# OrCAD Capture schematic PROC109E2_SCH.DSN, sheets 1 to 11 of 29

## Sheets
1 01. TABLE OF CONTENTS: title: TABLE OF CONTENTS; rev: E2
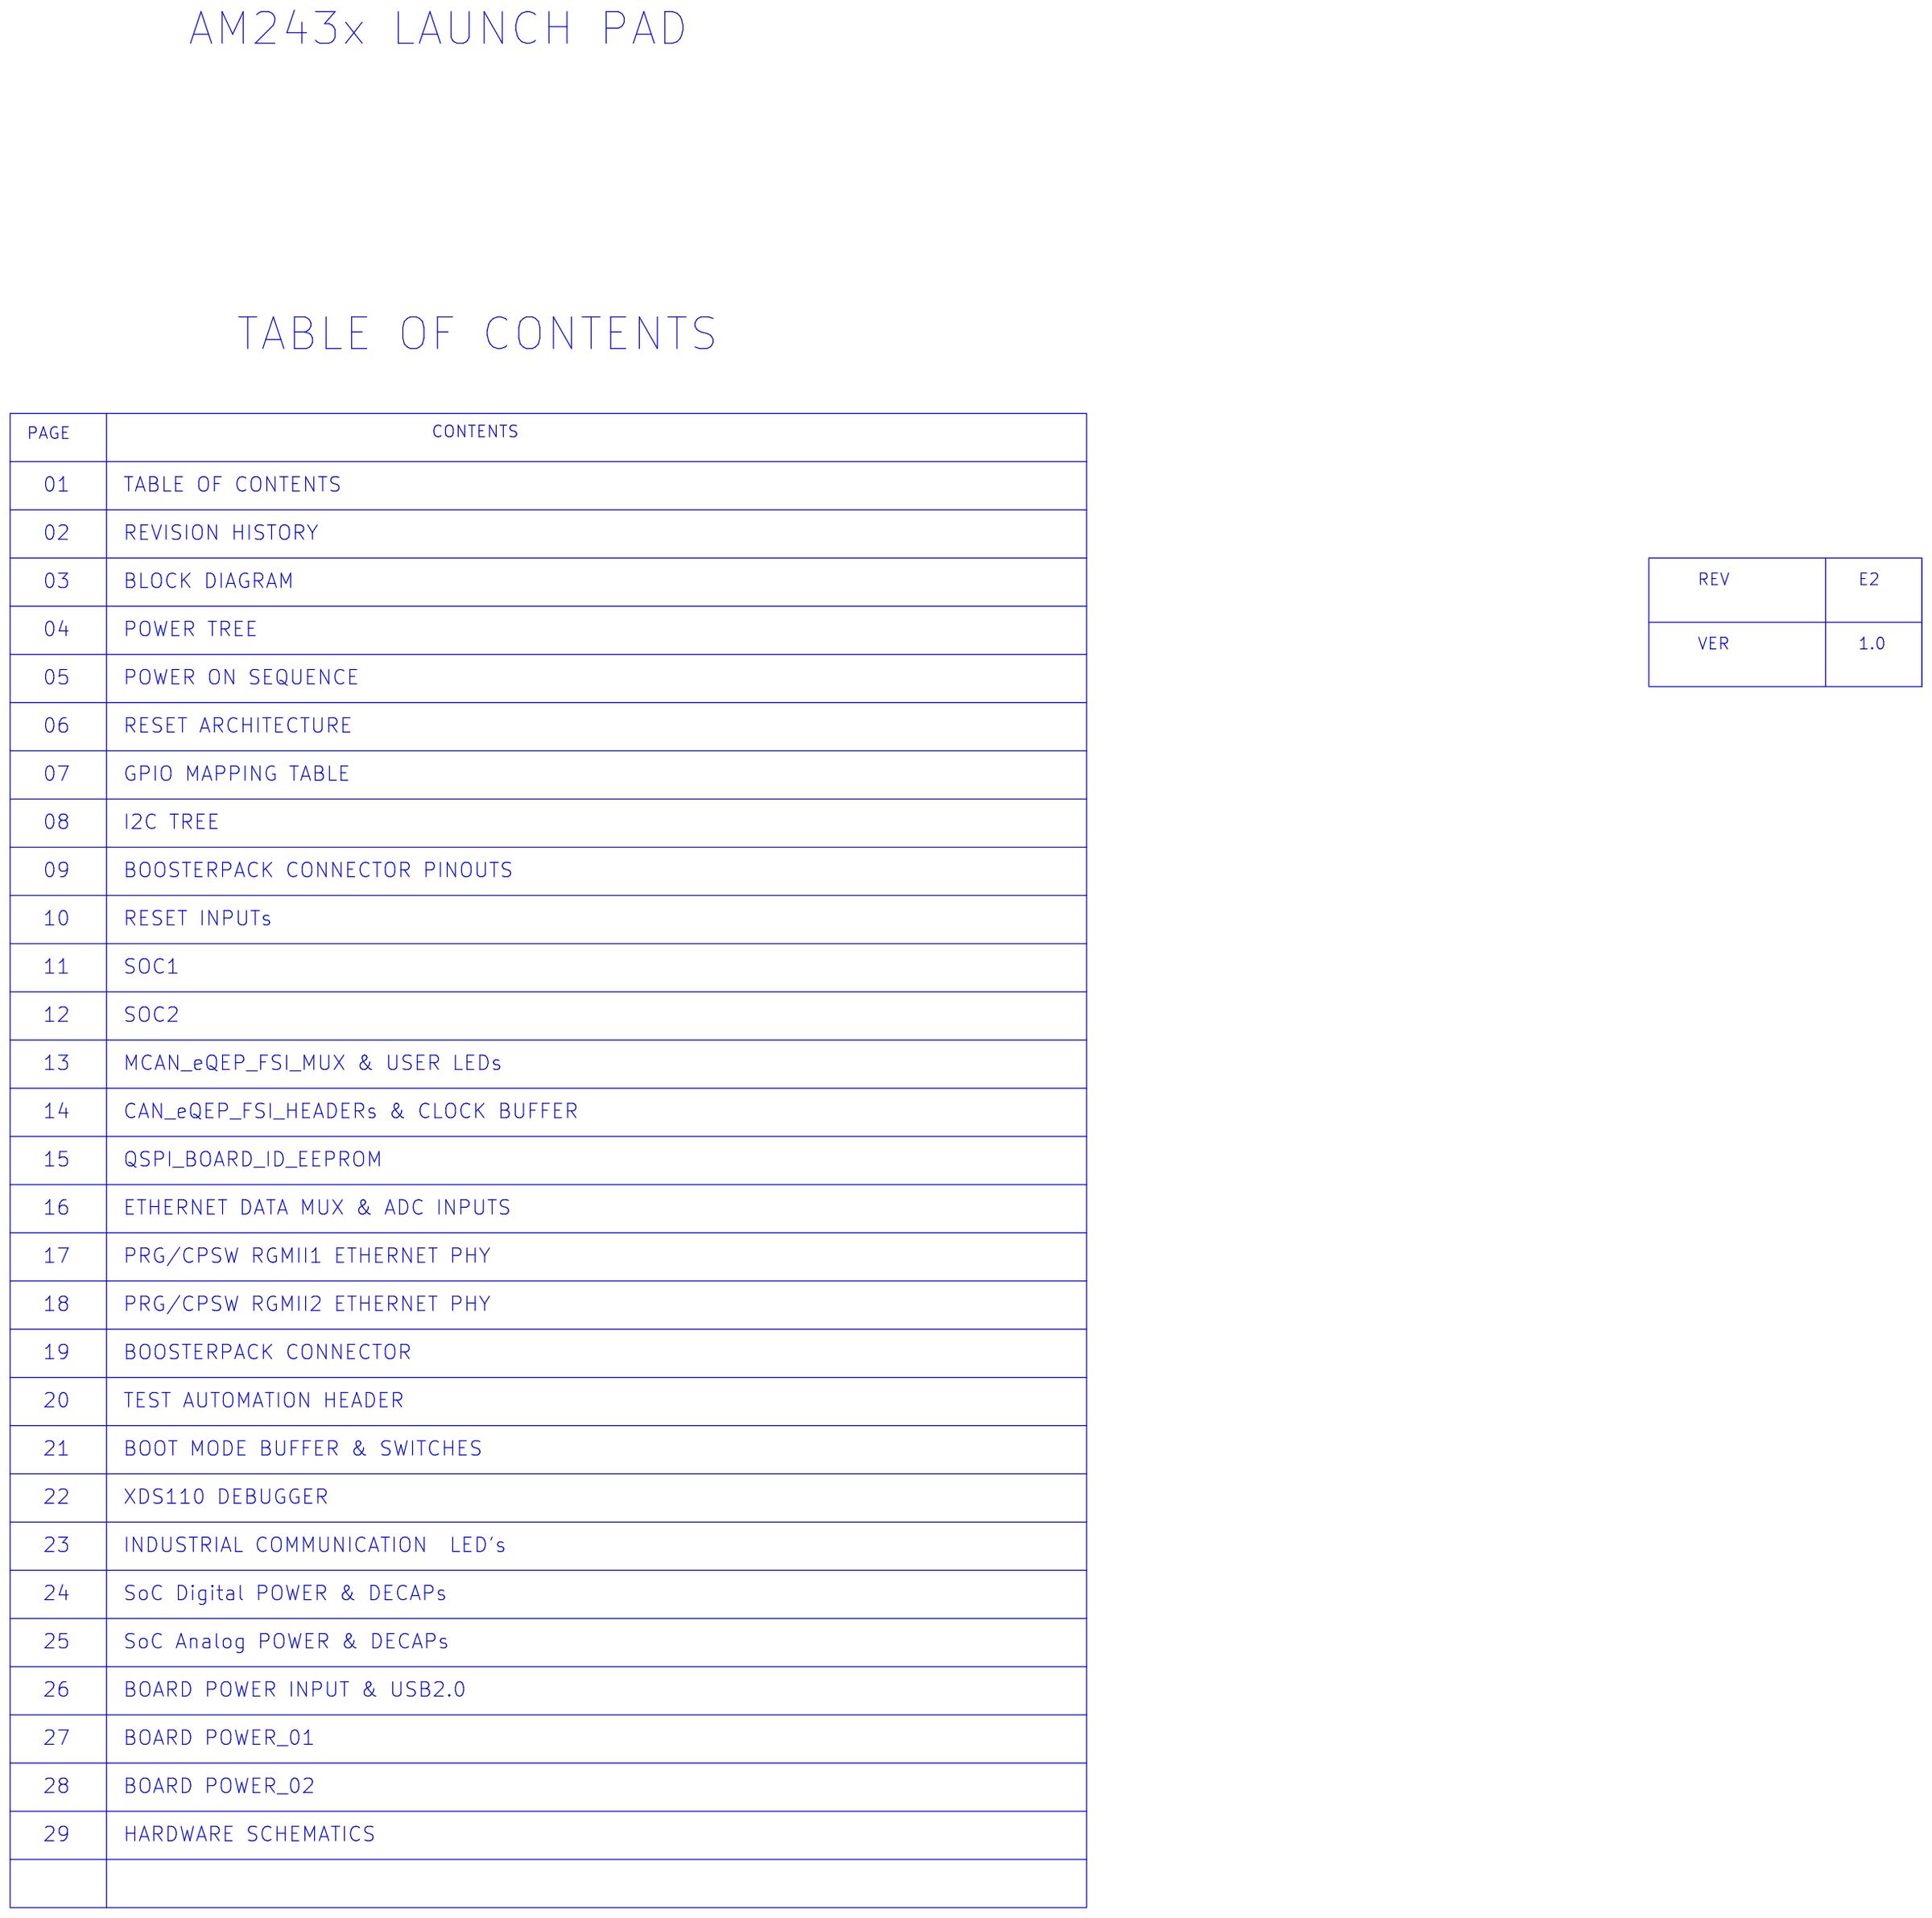
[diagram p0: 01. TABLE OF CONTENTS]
2 02. REVISION HISTORY: title: REVISION HISTORY
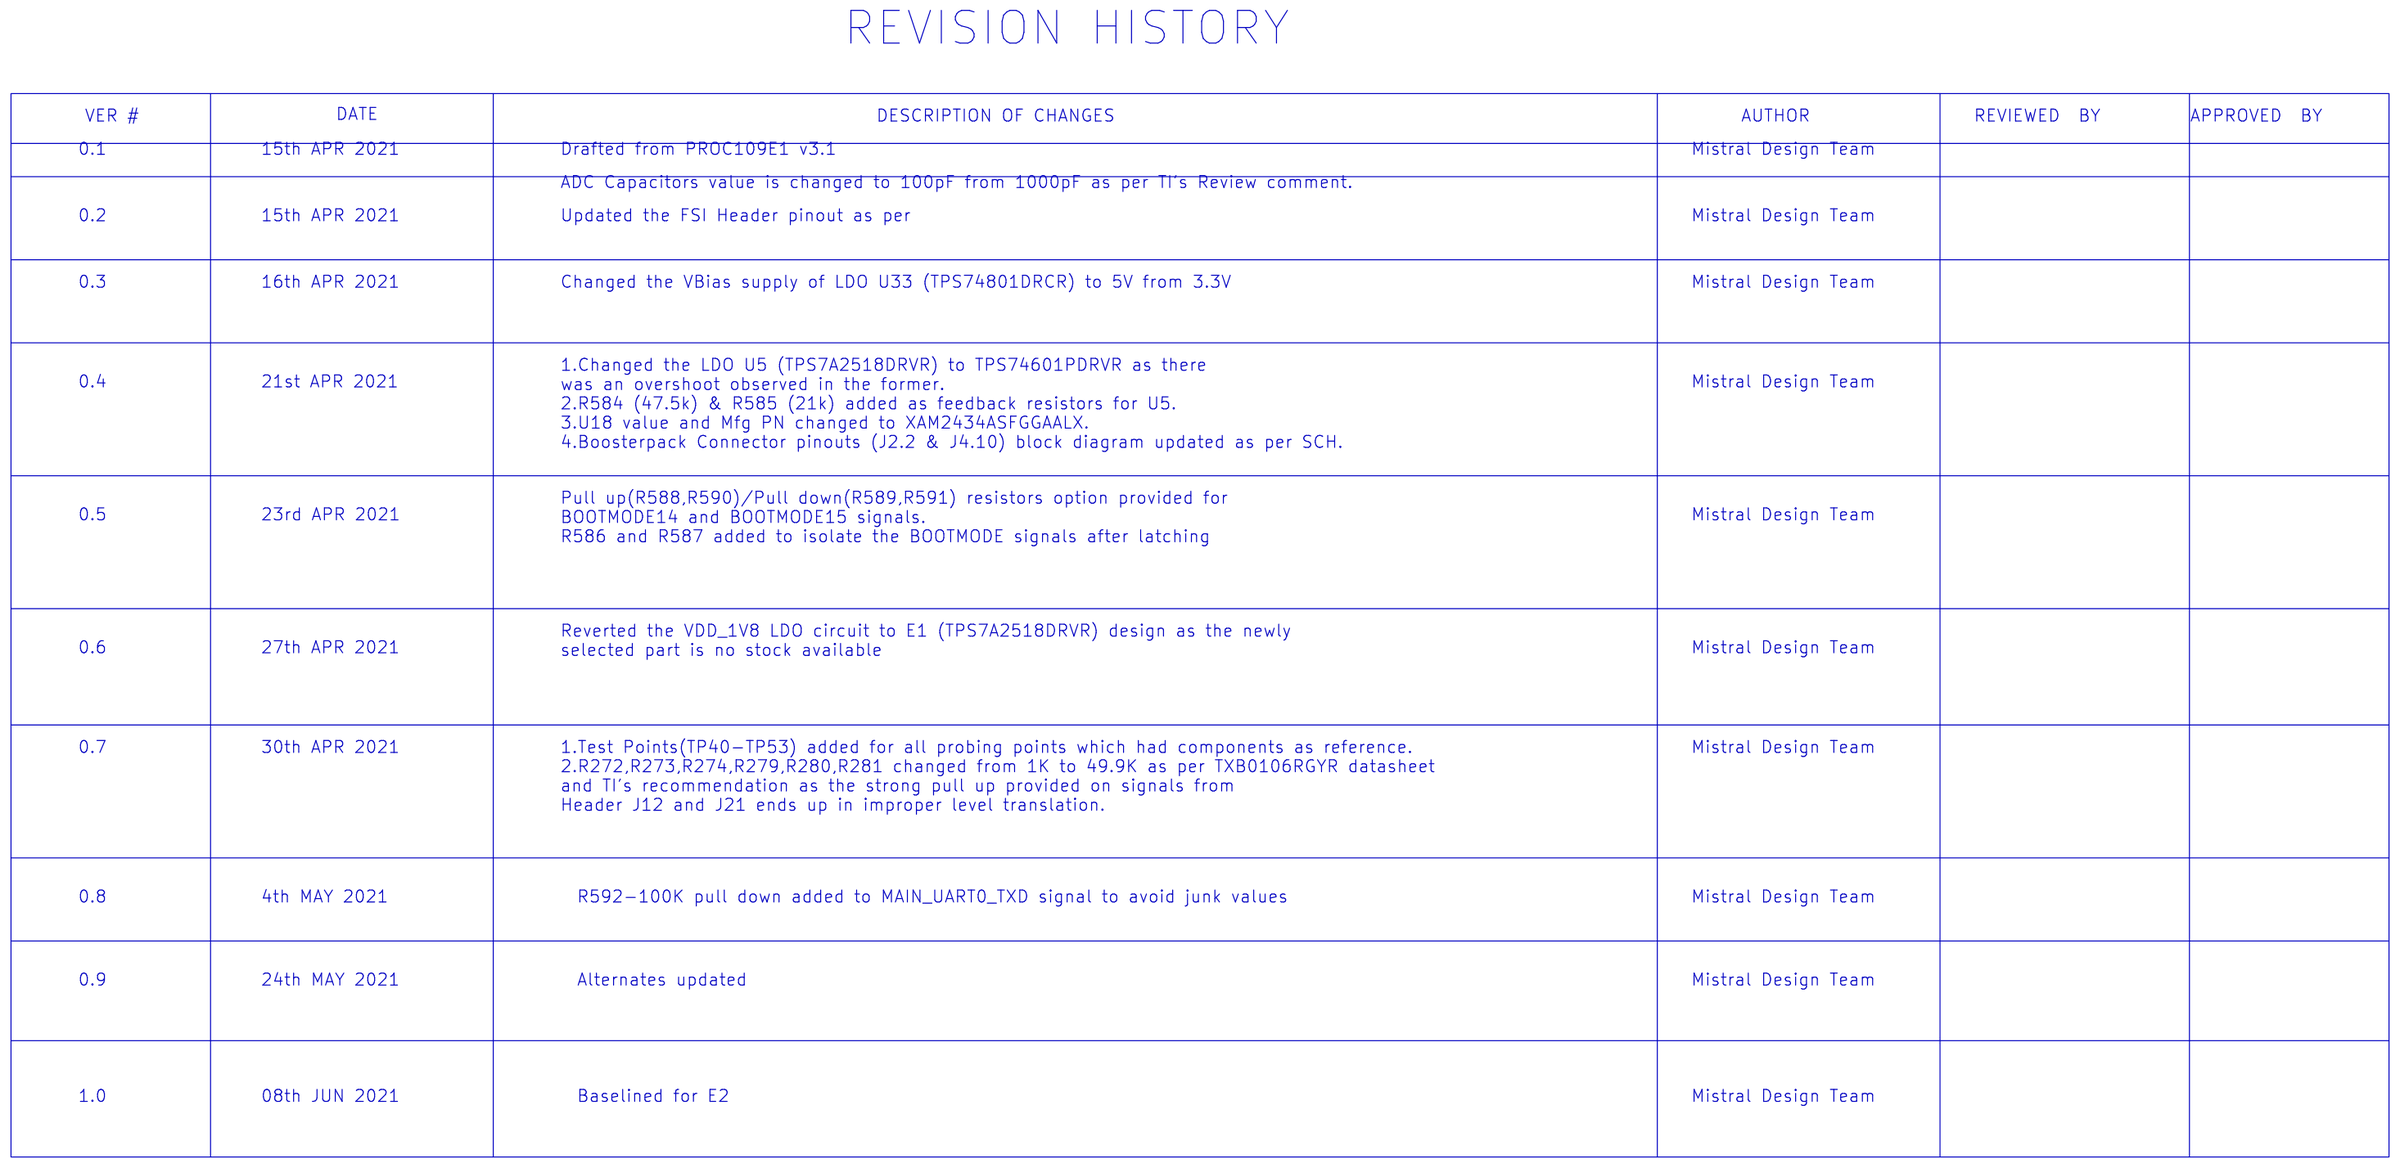
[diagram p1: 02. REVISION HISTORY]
3 03. BLOCK DIAGRAM: title: BLOCK DIAGRAM
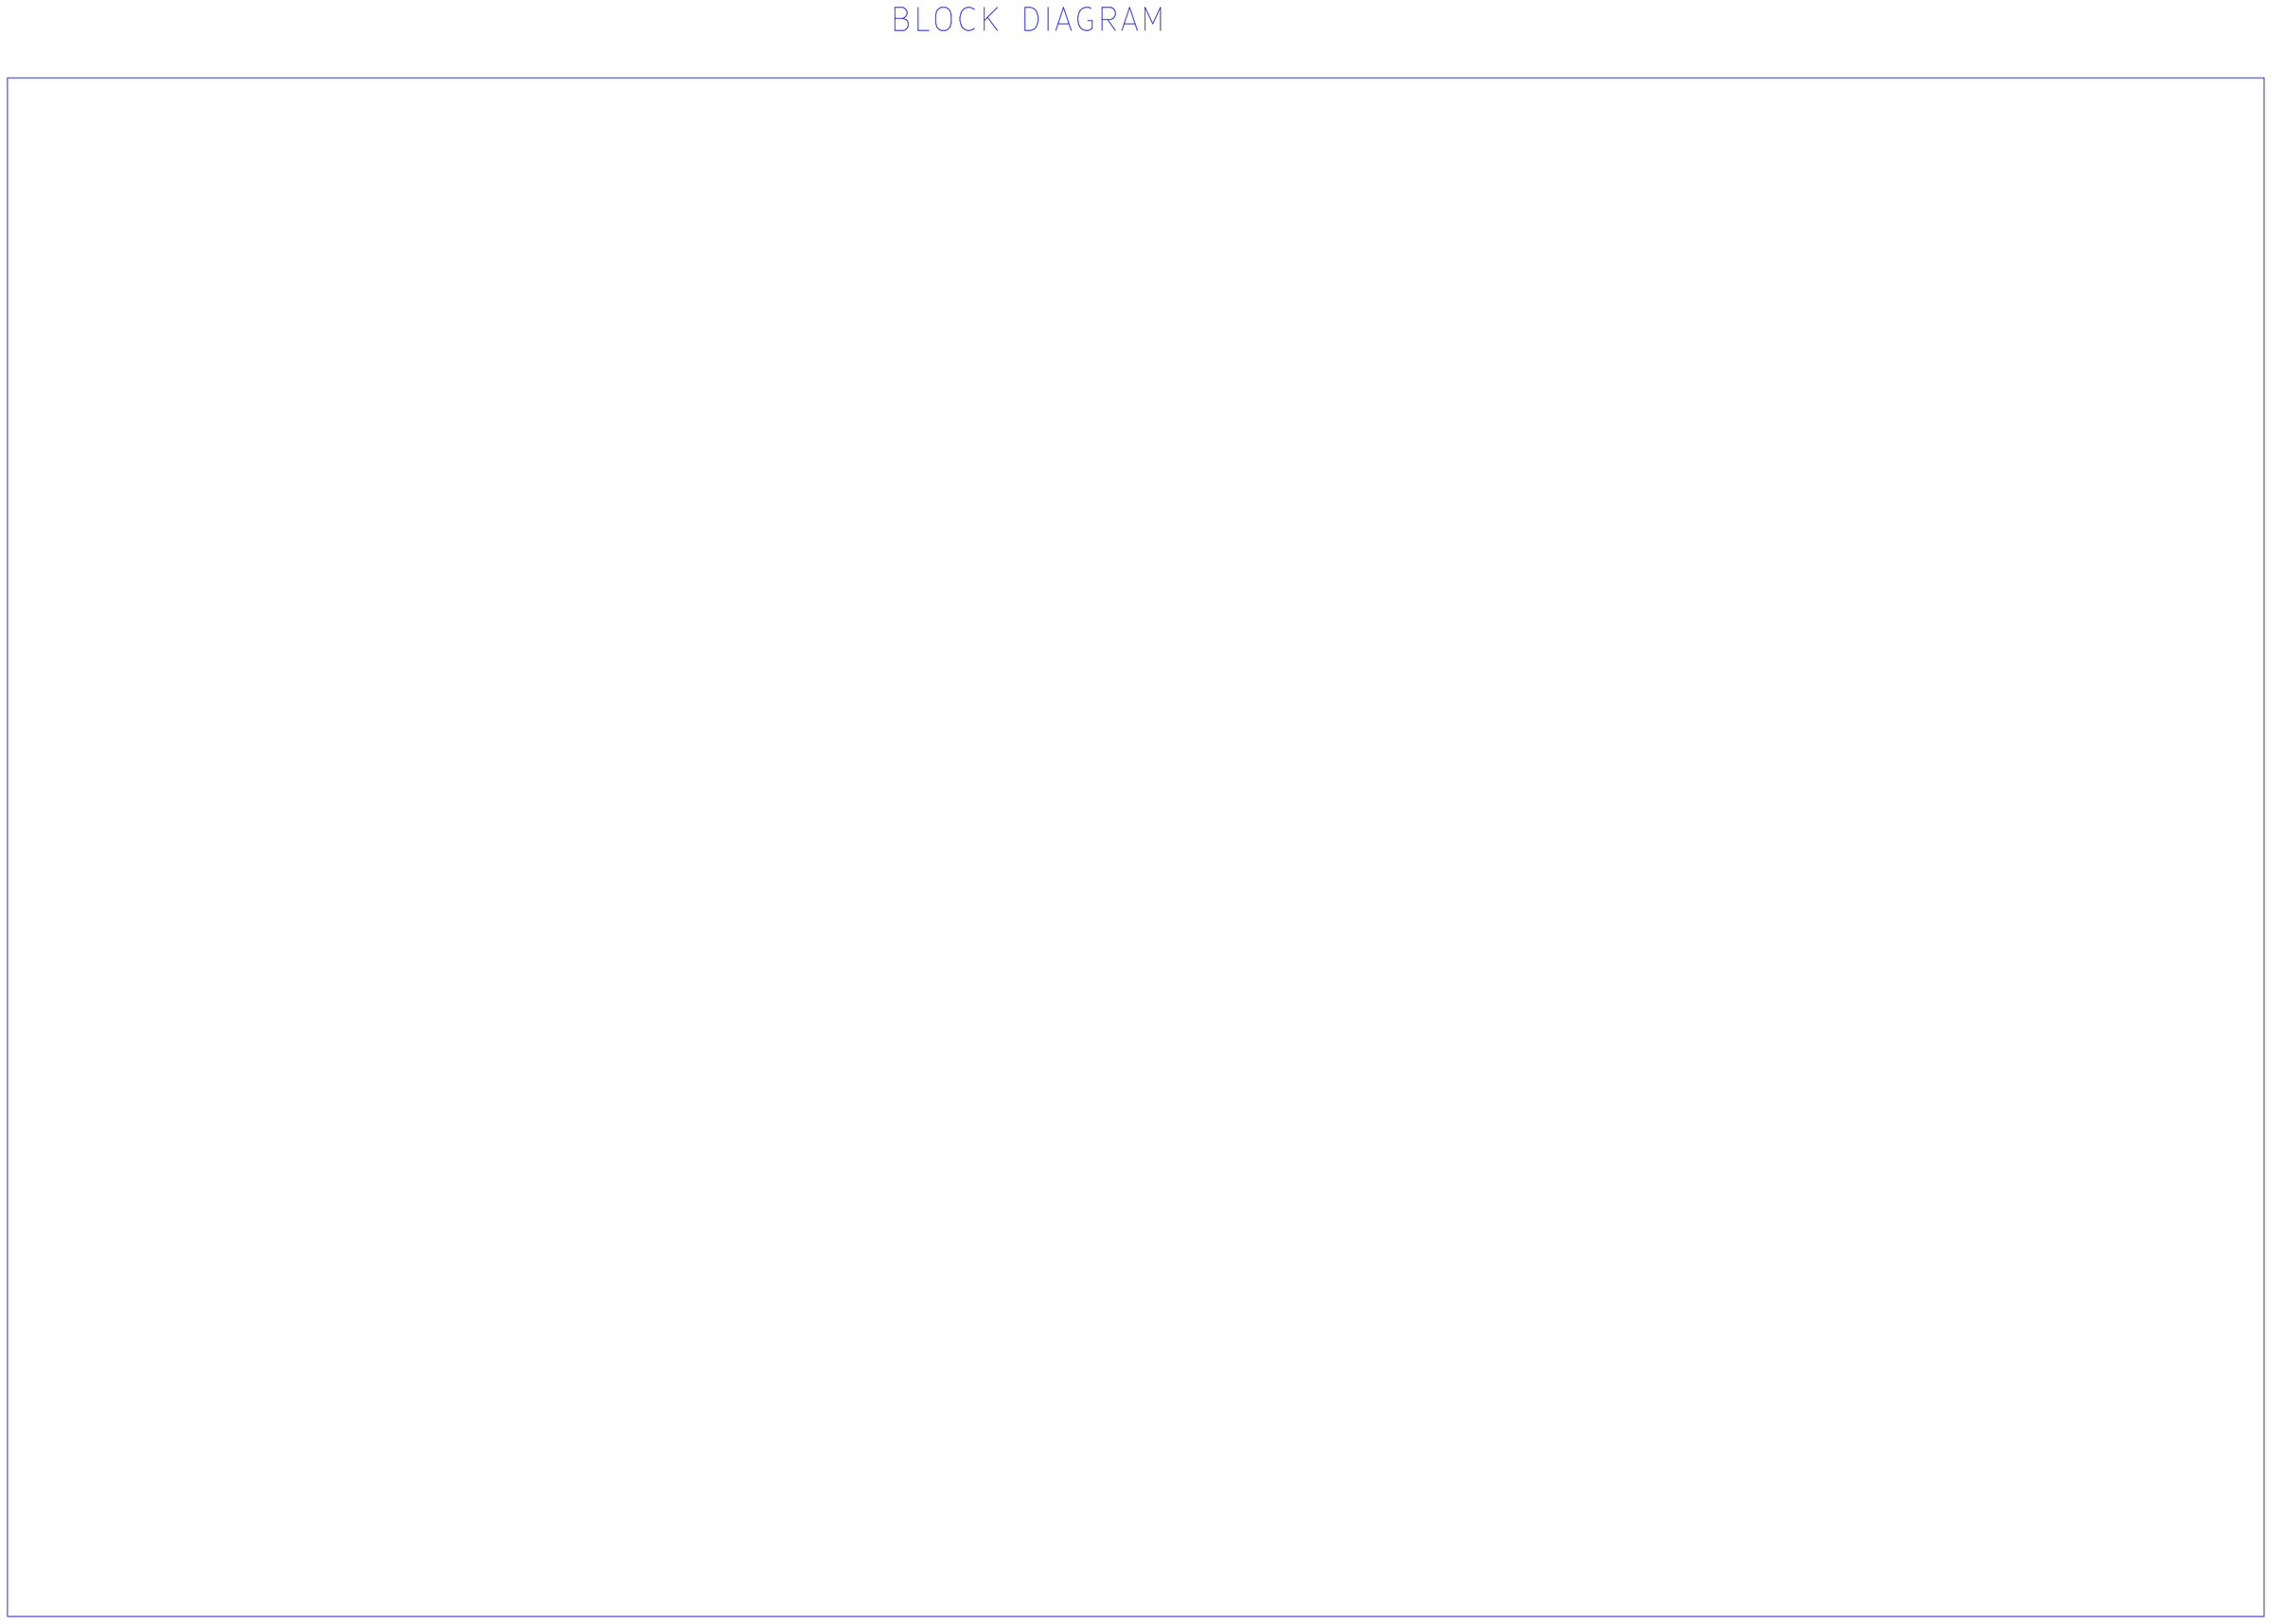
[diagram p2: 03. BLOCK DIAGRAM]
4 04. POWER TREE: title: POWER TREE
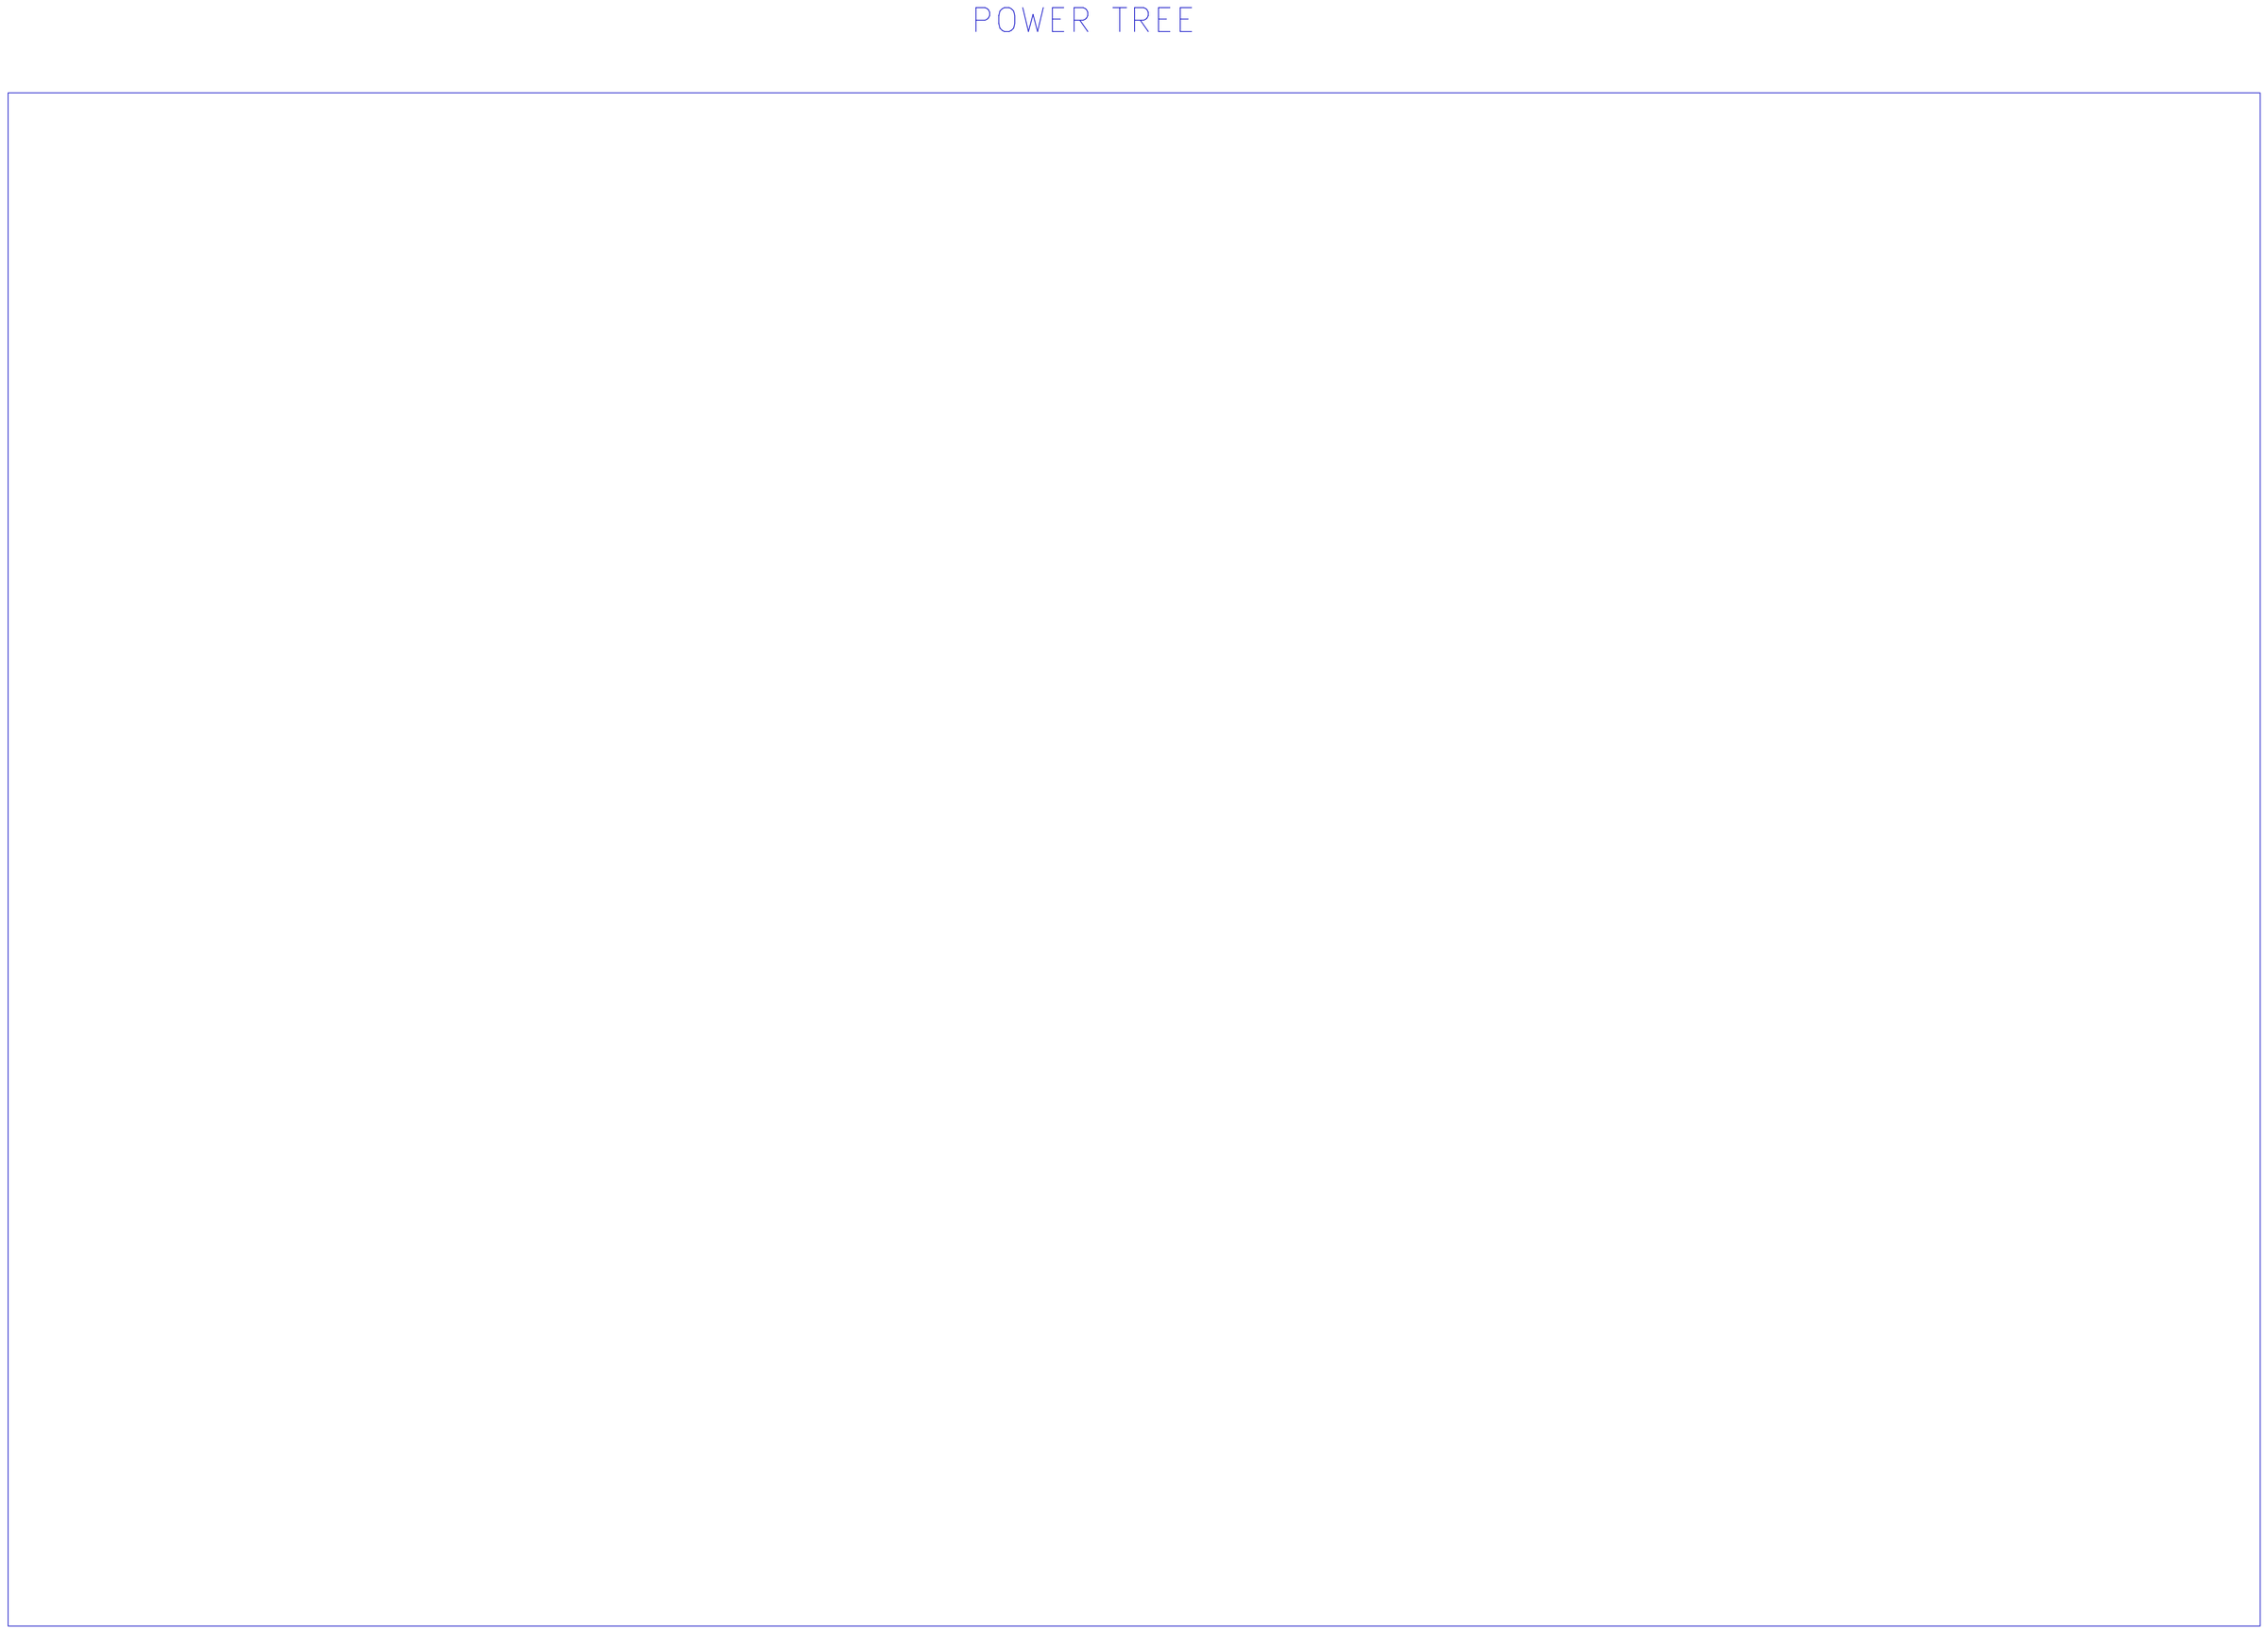
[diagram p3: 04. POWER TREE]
5 05. POWER ON SEQUENCE: title: POWER ON SEQUENCE
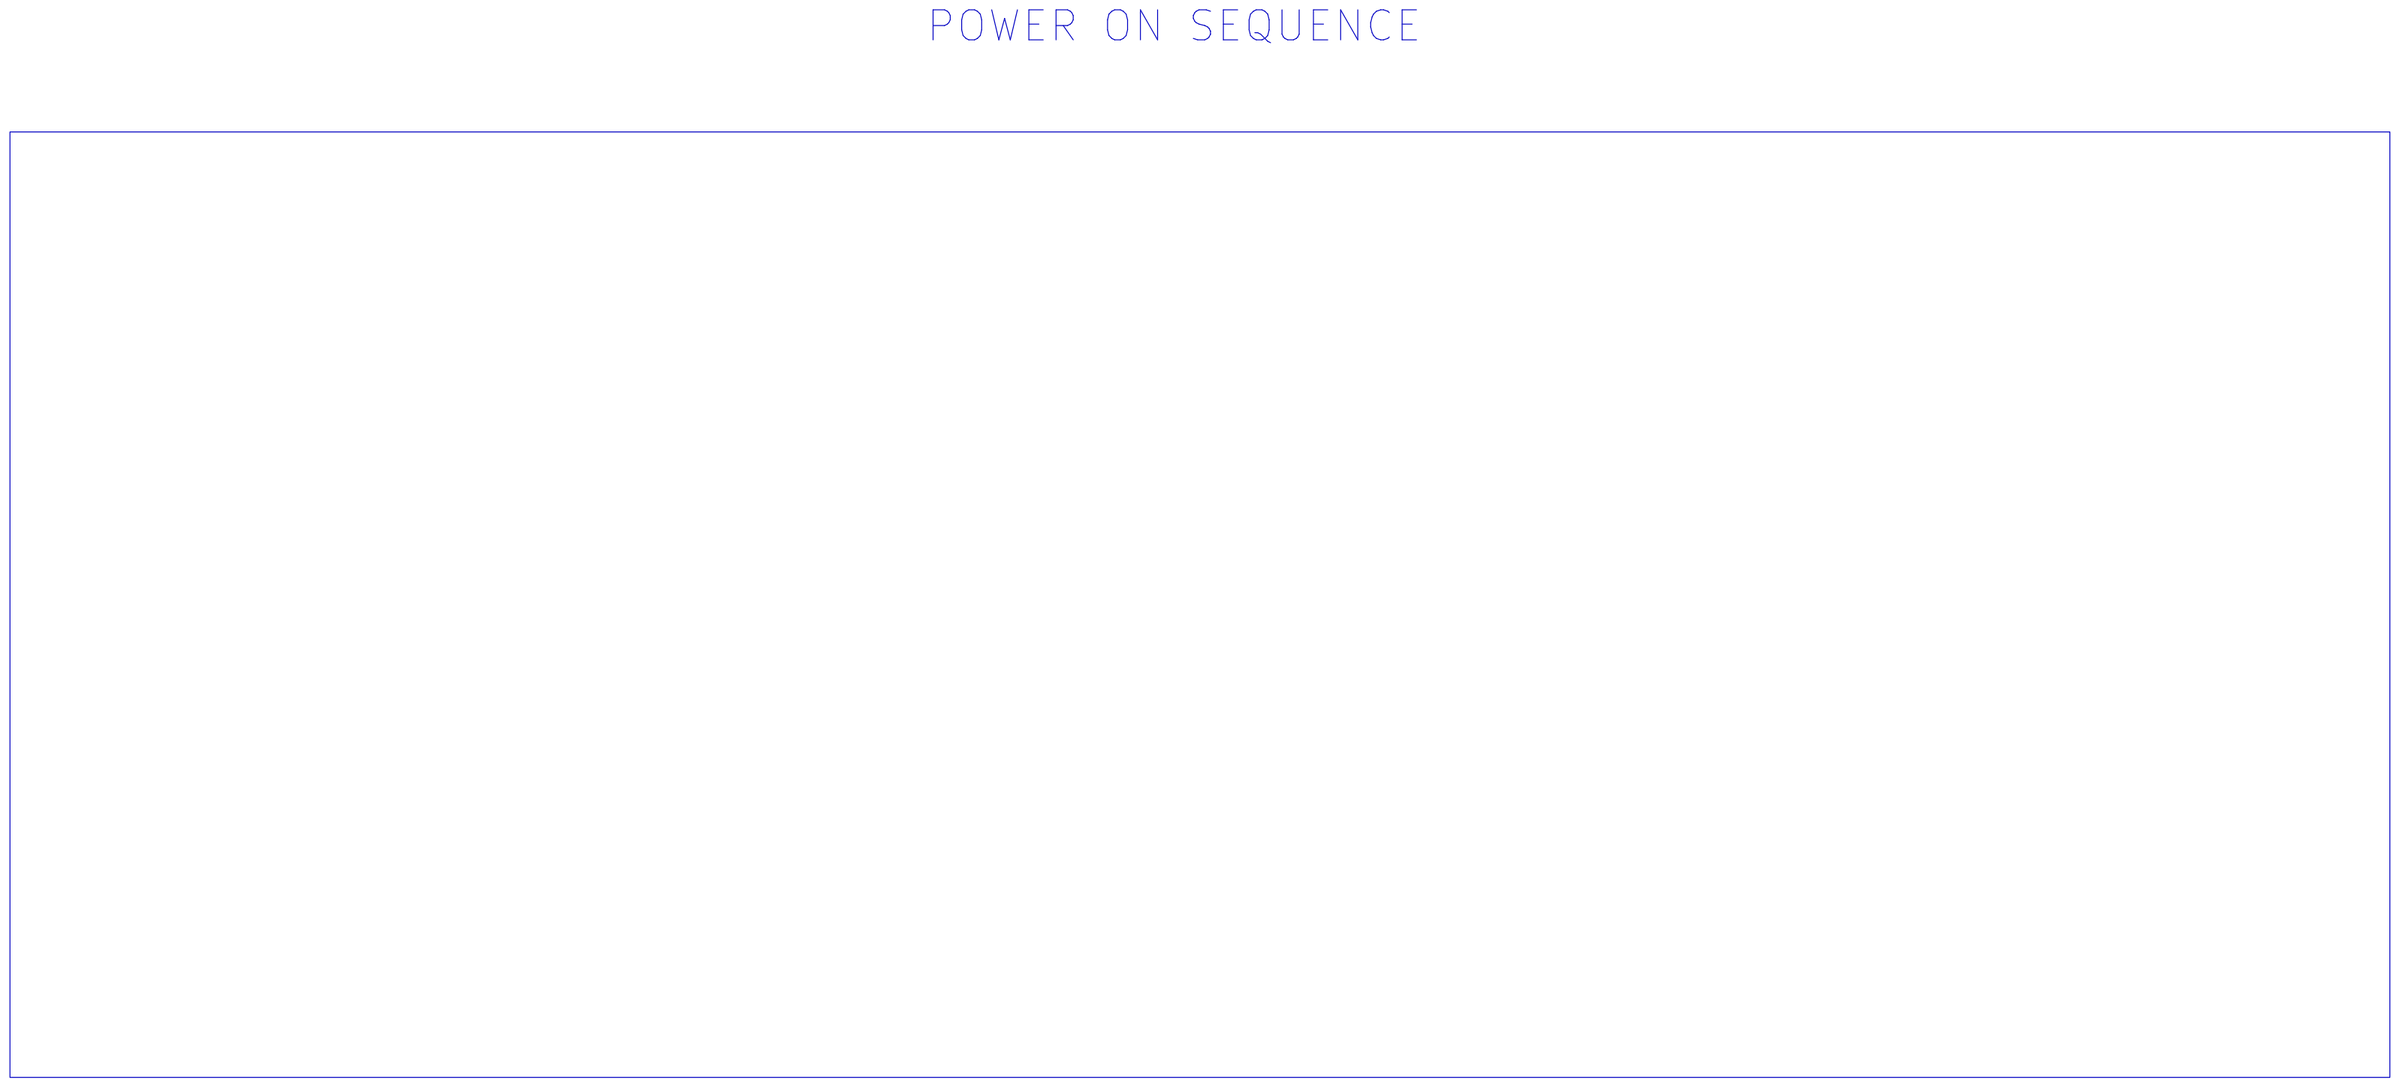
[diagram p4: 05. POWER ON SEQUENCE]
6 06. RESET ARCHITECTURE: title: RESET ARCHITECTURE
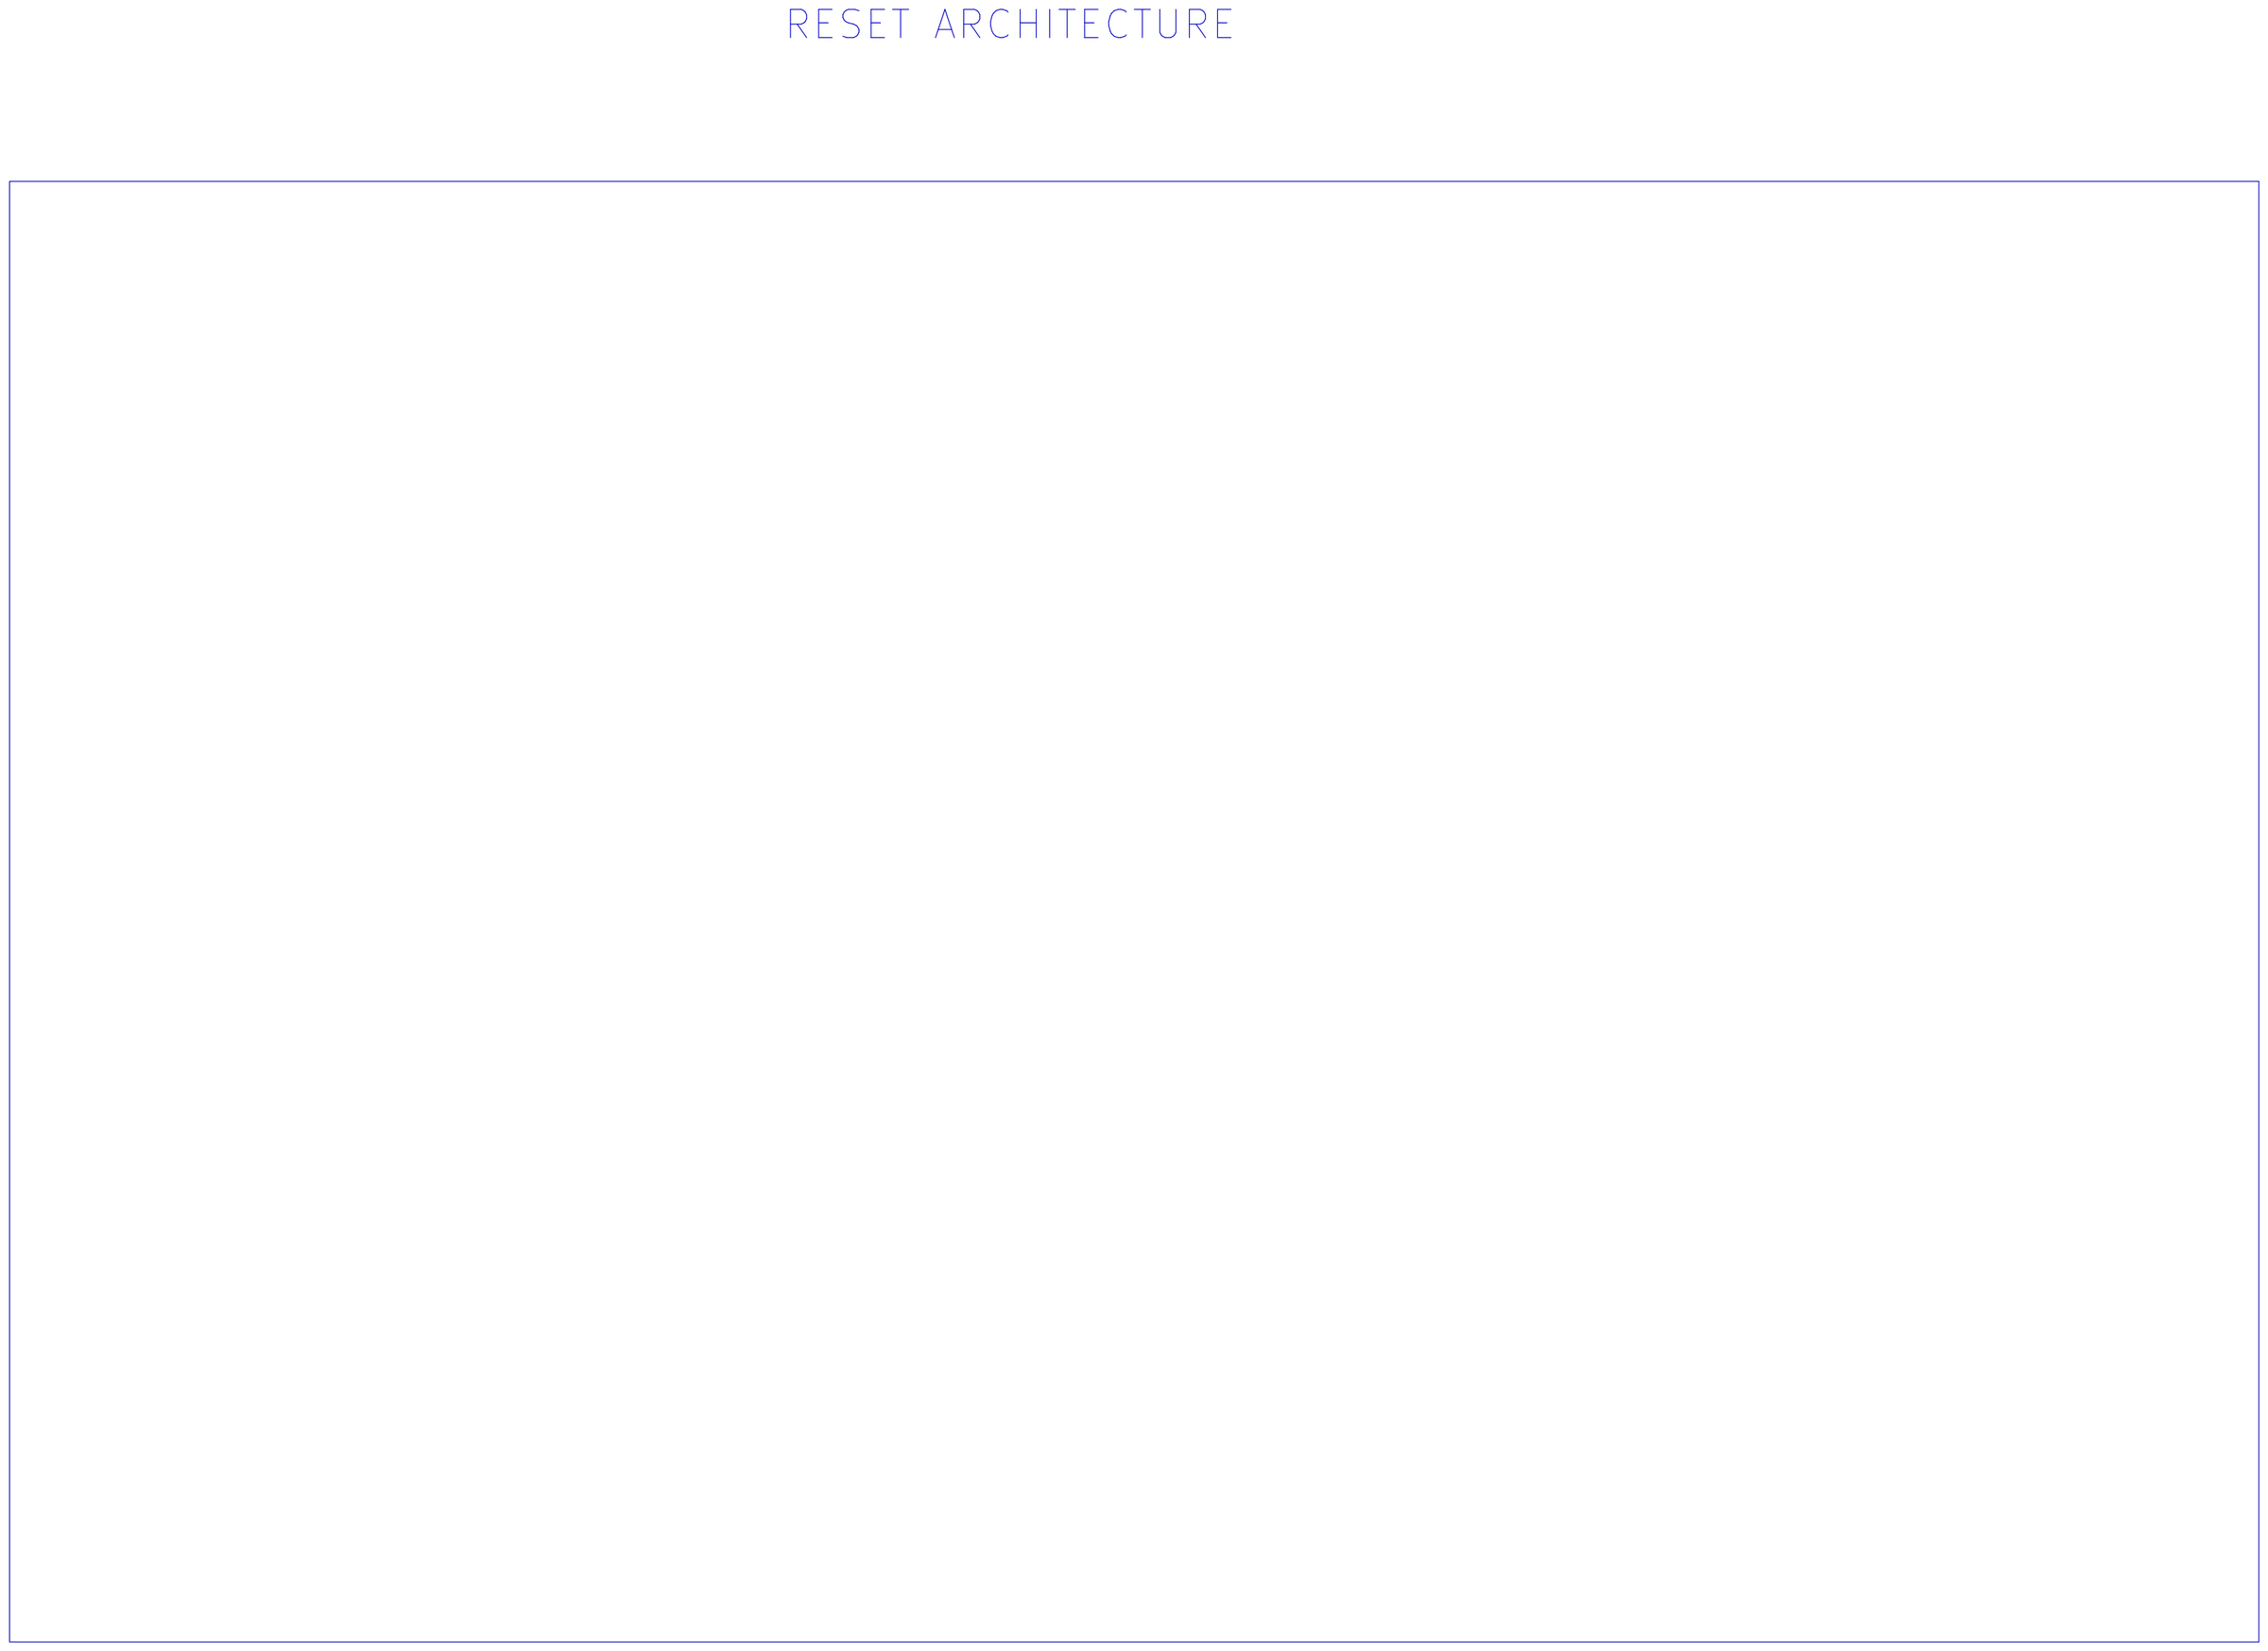
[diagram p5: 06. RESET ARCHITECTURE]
7 07. GPIO MAPPING TABLE: title: GPIO MAPPING TABLE
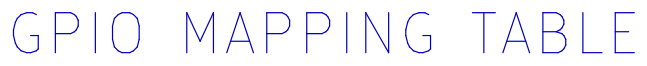
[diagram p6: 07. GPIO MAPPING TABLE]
8 08. I2C TREE: title: I2C TREE
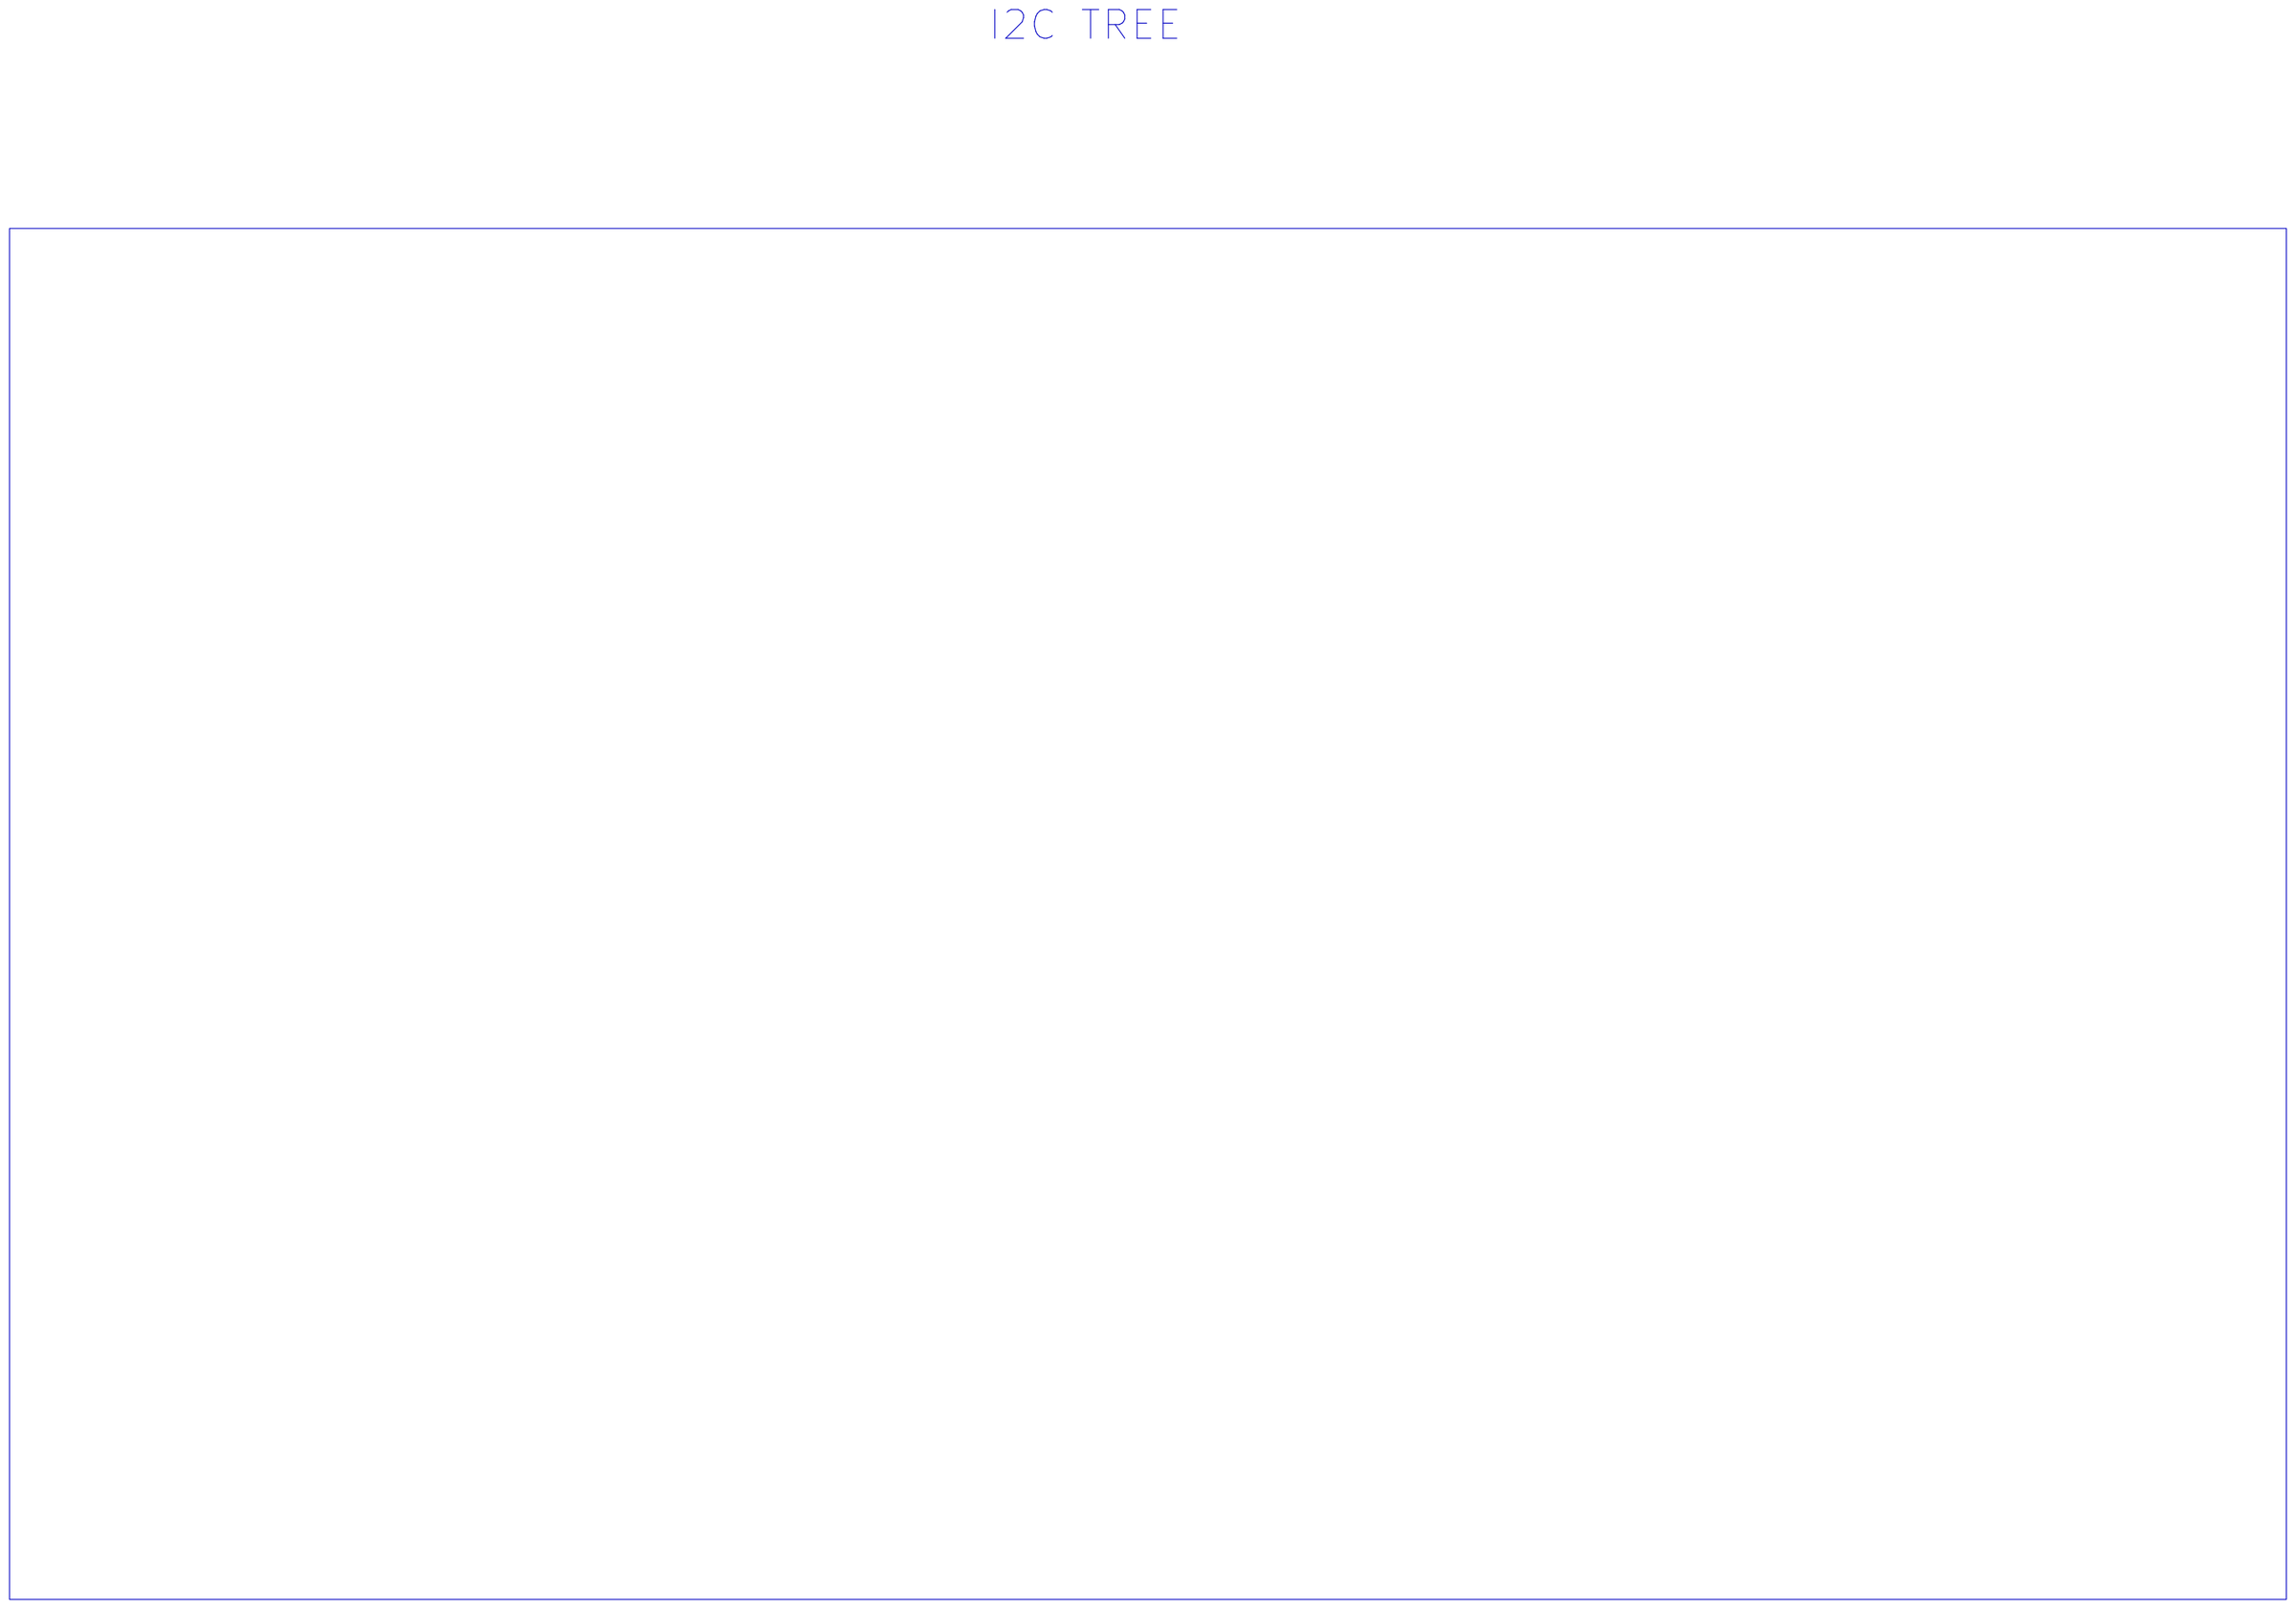
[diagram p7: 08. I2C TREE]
9 09. BOOSTERPACK CONN PINOUTs: title: BOOSTERPACK CONNECTOR PINOUTS
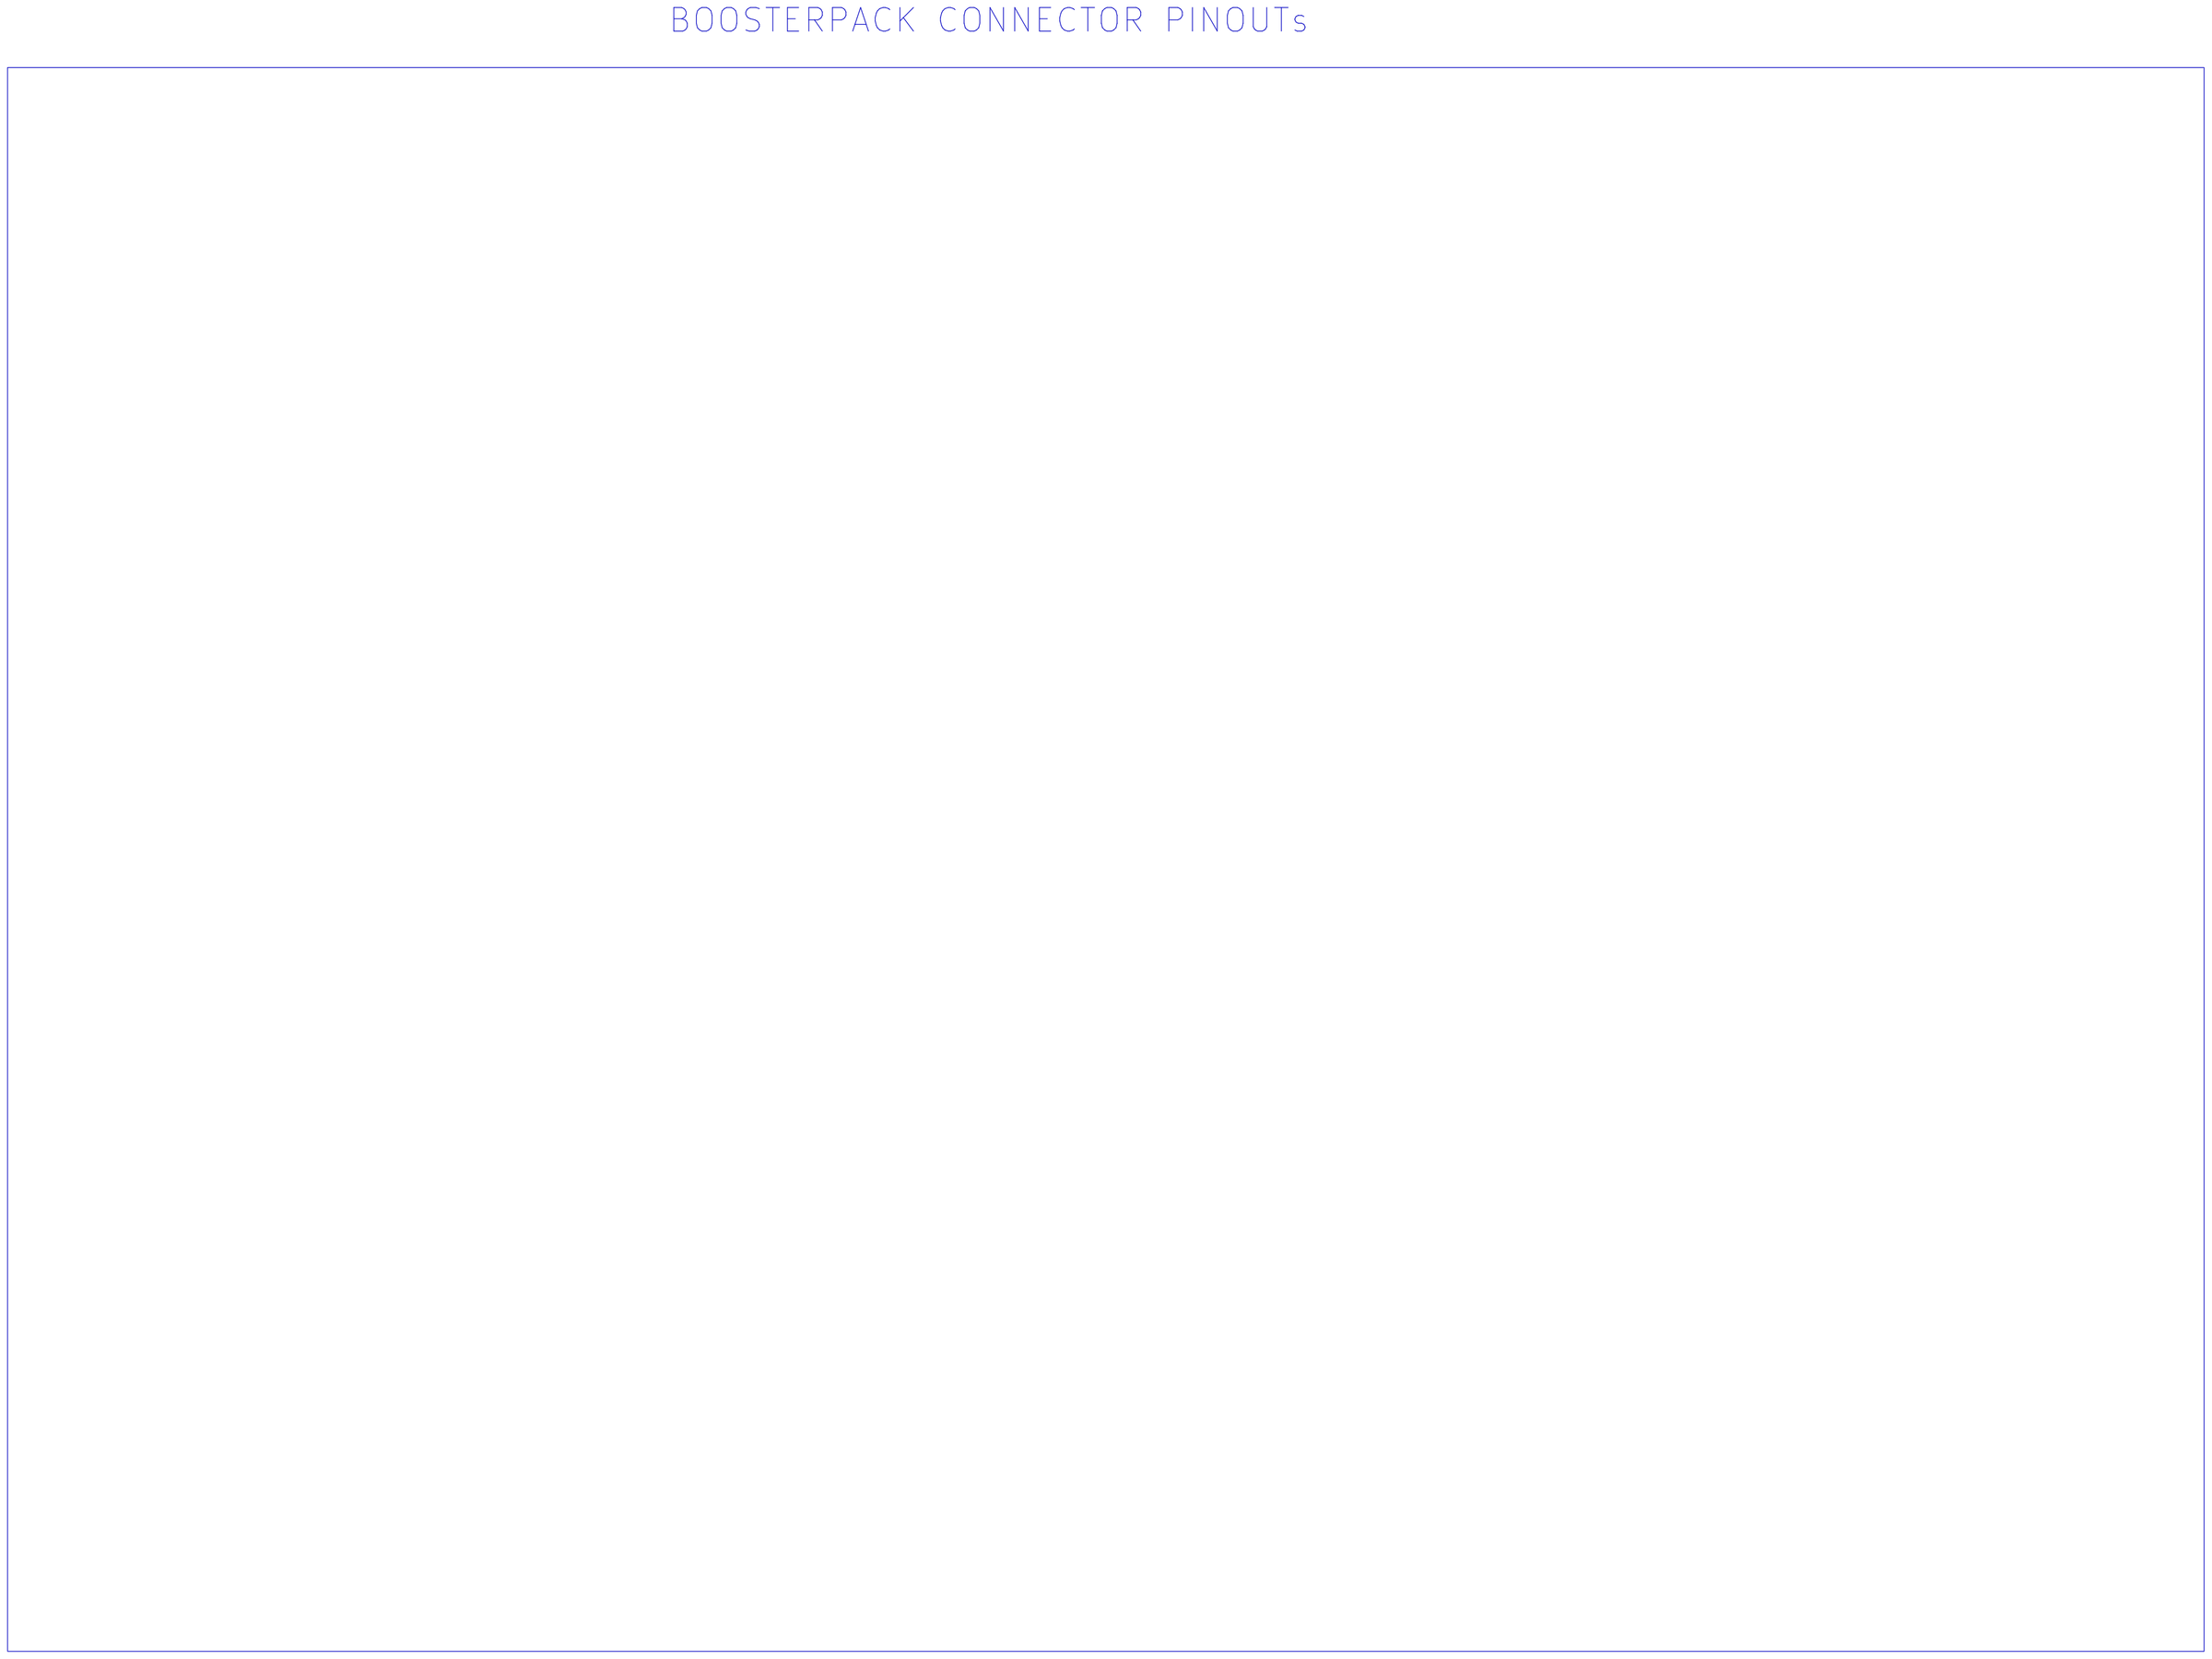
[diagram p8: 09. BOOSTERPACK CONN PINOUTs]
10 10. RESET_INPUTs: size C; title: RESET INPUTs
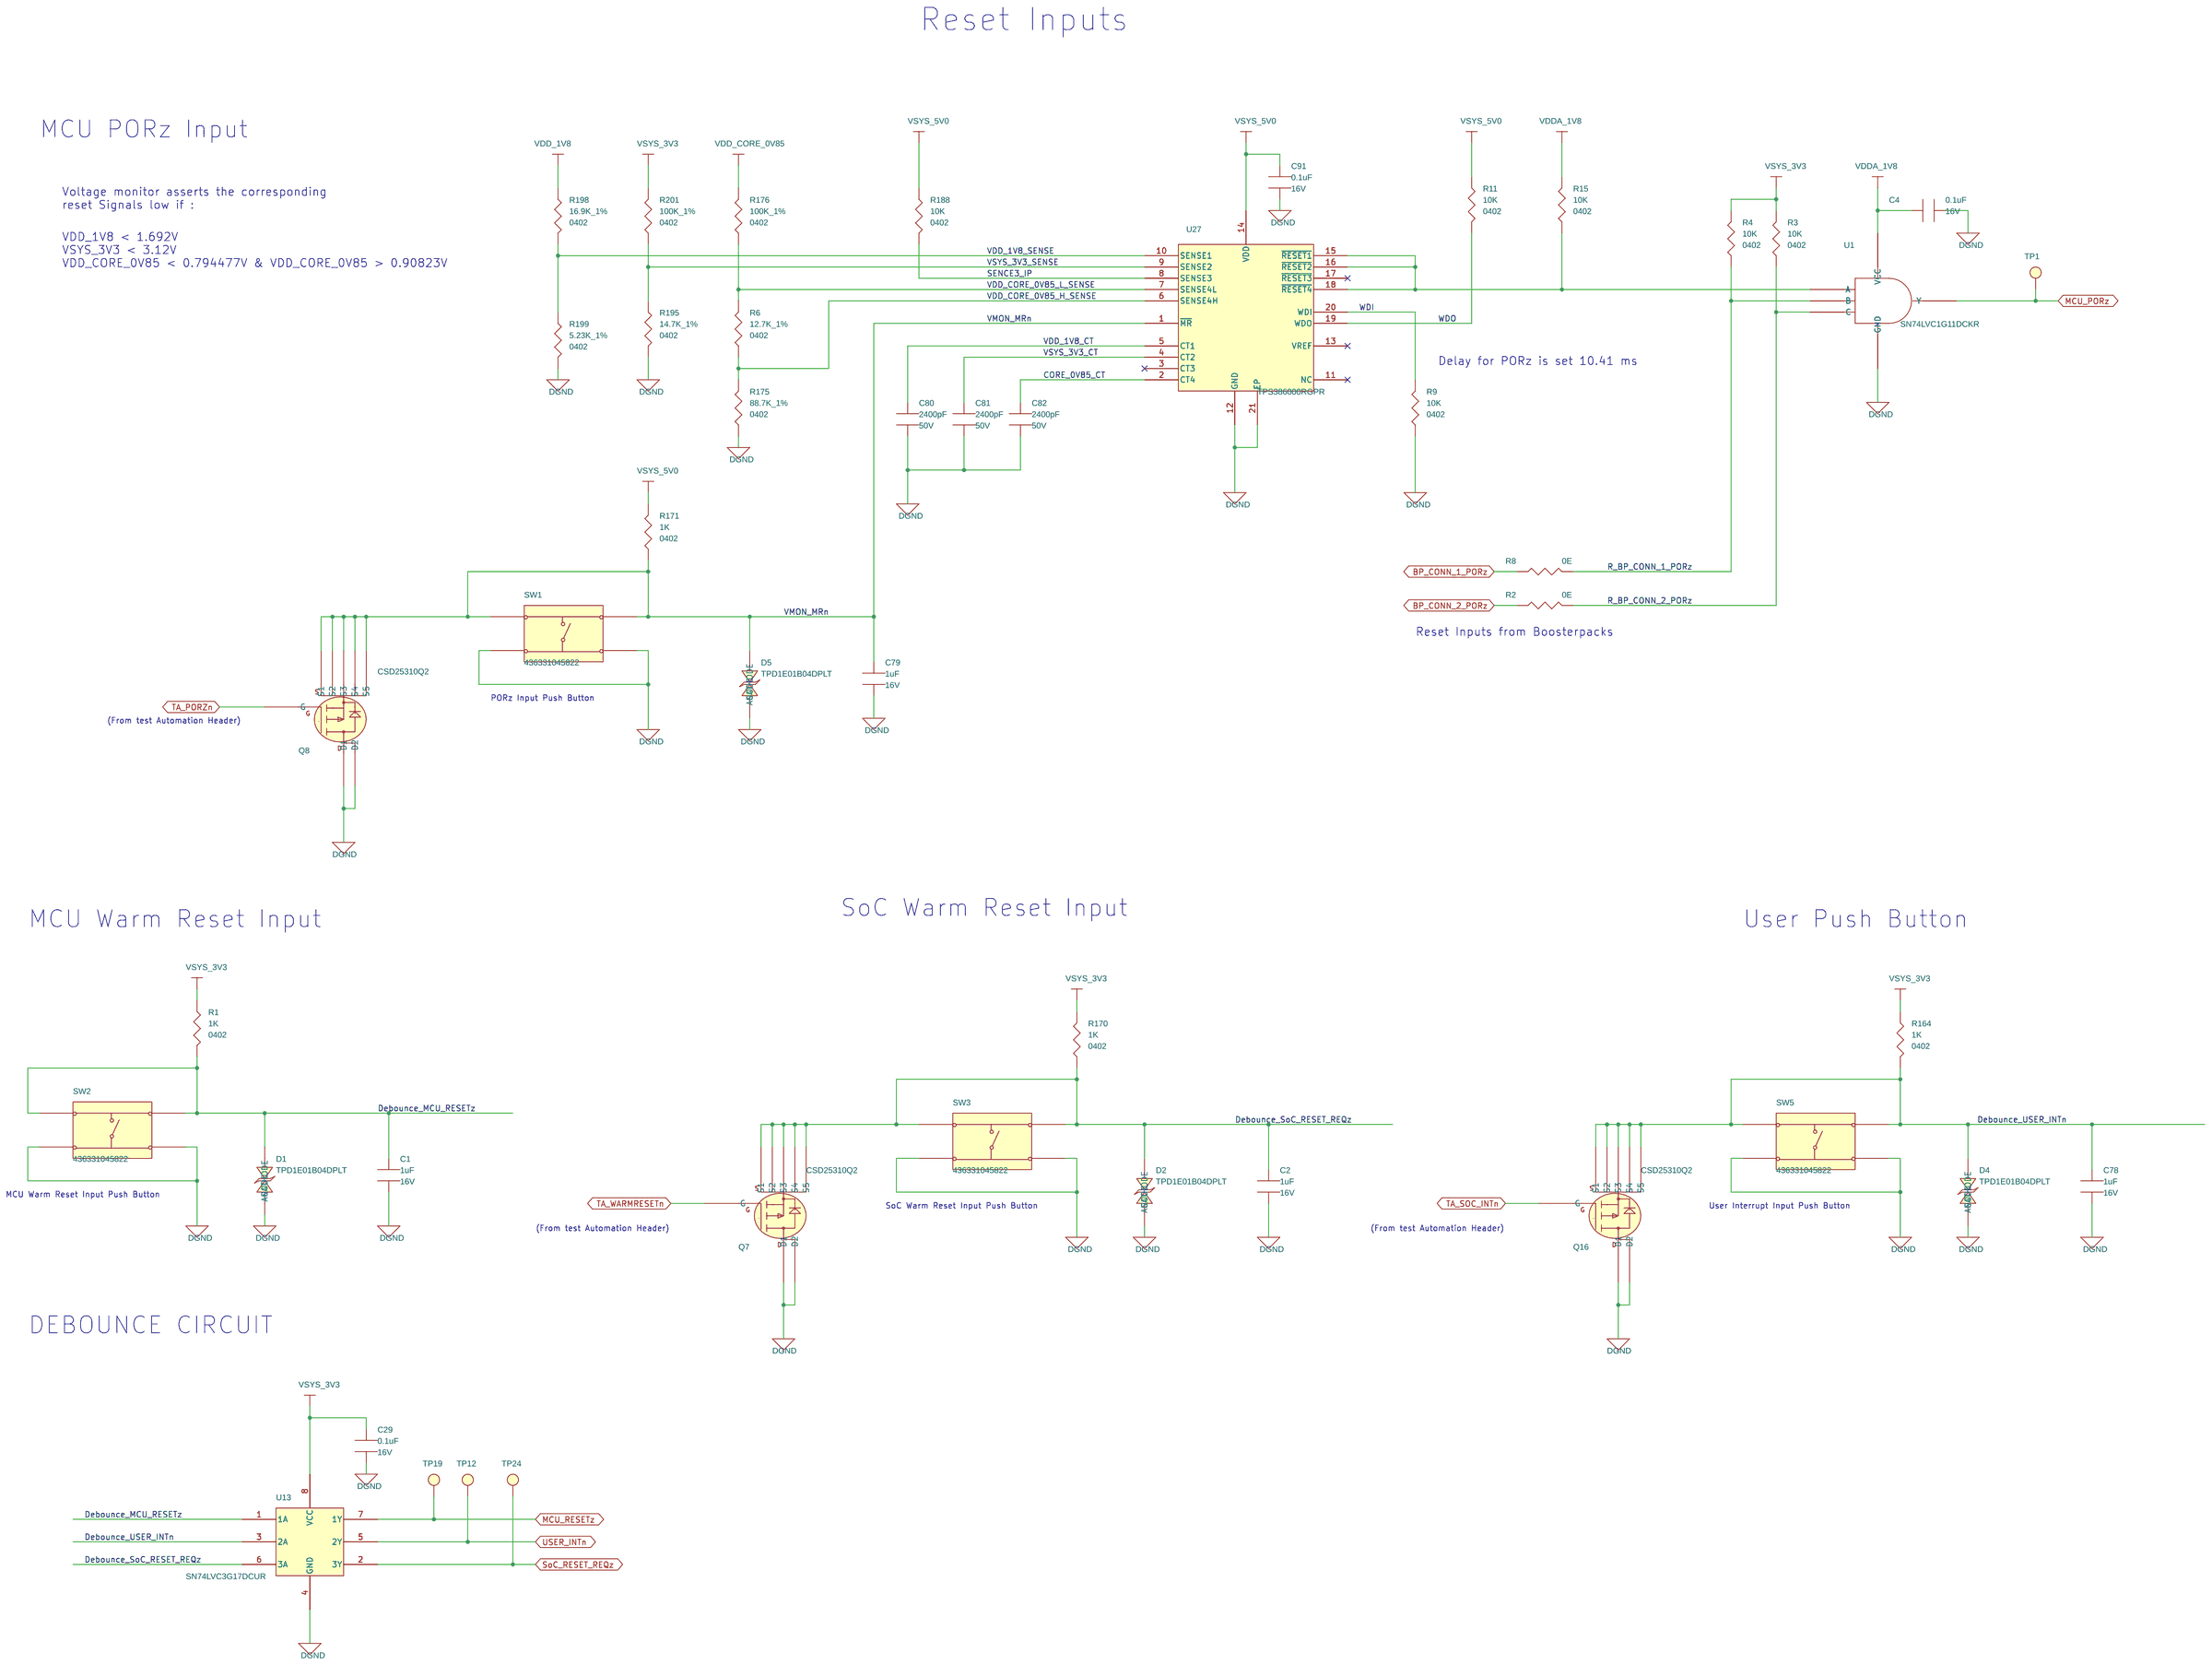
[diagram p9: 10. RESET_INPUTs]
11 11. SOC1: size C; title: SOC1
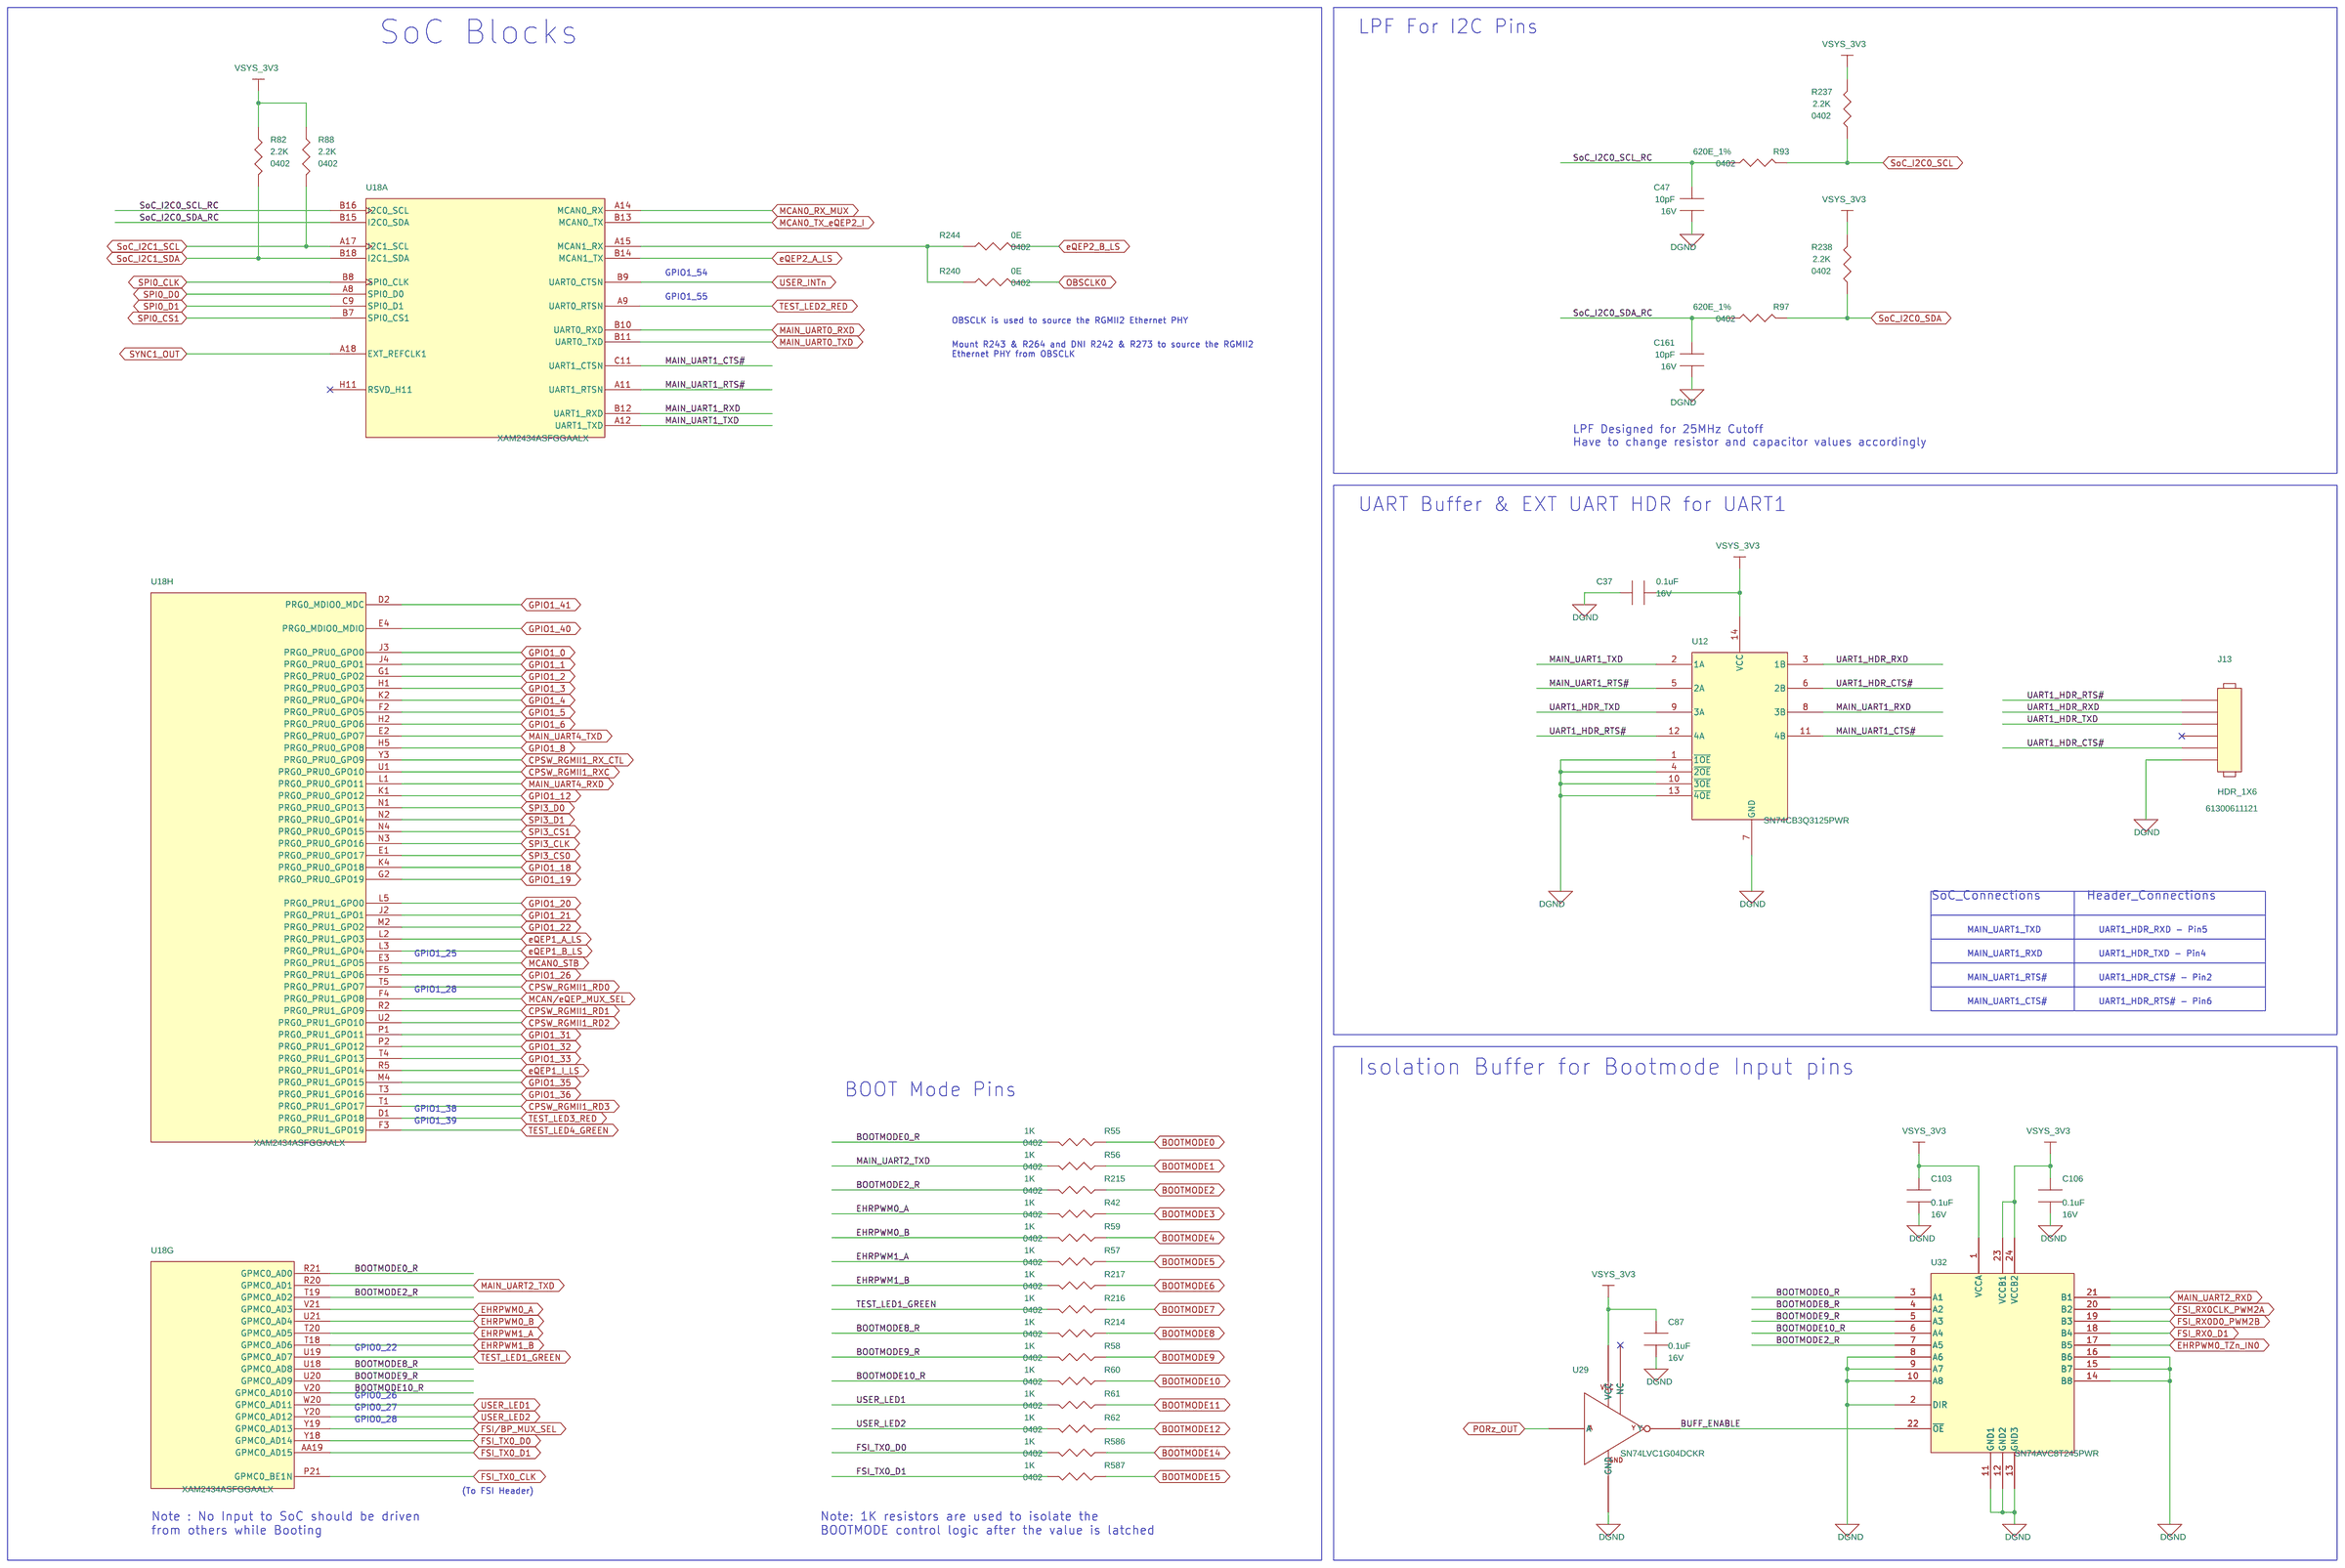
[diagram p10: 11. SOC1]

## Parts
sheet 10. RESET_INPUTs
C1  1uF  [CAP0201_0-5]
C2  1uF  [CAP0201_0-5]
C4  0.1uF  [CAP0201_0-5]
C29  0.1uF  [CAP0201_0-5]
C78  1uF  [CAP0201_0-5]
C79  1uF  [CAP0201_0-5]
C80  2400pF  [CAP0603_1]
C81  2400pF  [CAP0603_1]
C82  2400pF  [CAP0603_1]
C91  0.1uF  [CAP0201_0-5]
D1  TPD1E01B04DPLT  [DIO_DFN0201_0-4]
D2  TPD1E01B04DPLT  [DIO_DFN0201_0-4]
D4  TPD1E01B04DPLT  [DIO_DFN0201_0-4]
D5  TPD1E01B04DPLT  [DIO_DFN0201_0-4]
Q7  CSD25310Q2  [SON6_CSD17313Q2_80X80]
Q8  CSD25310Q2  [SON6_CSD17313Q2_80X80]
Q16  CSD25310Q2  [SON6_CSD17313Q2_80X80]
R1  1K  [RES0402_0-5]
R2  0E  [RES0402_0-5]
R3  10K  [RES0402_0-5]
R4  10K  [RES0402_0-5]
R6  12.7K_1%  [RES0402_0-5]
R8  0E  [RES0402_0-5]
R9  10K  [RES0402_0-5]
R11  10K  [RES0402_0-5]
R15  10K  [RES0402_0-5]
R164  1K  [RES0402_0-5]
R170  1K  [RES0402_0-5]
R171  1K  [RES0402_0-5]
R175  88.7K_1%  [RES0402_0-5]
R176  100K_1%  [RES0402_0-5]
R188  10K  [RES0402_0-5]
R195  14.7K_1%  [RES0402_0-5]
R198  16.9K_1%  [RES0402_0-5]
R199  5.23K_1%  [RES0402_0-5]
R201  100K_1%  [RES0402_0-5]
SW1  436331045822  [SW4_436331045822_190X190_SMD_1-7]
SW2  436331045822  [SW4_436331045822_190X190_SMD_1-7]
SW3  436331045822  [SW4_436331045822_190X190_SMD_1-7]
SW5  436331045822  [SW4_436331045822_190X190_SMD_1-7]
TP1  TP20_SMD  [TP20_SMD]
TP12  TP20_SMD  [TP20_SMD]
TP19  TP20_SMD  [TP20_SMD]
TP24  TP20_SMD  [TP20_SMD]
U1  SN74LVC1G11DCKR  [SC70-6]
U13  SN74LVC3G17DCUR  [VSSOP8_19-68_85X95_0-9]
U27  TPS386000RGPR  [QFN20_19-68_160X160_1]
sheet 11. SOC1
C37  0.1uF  [CAP0201_0-5]
C47  10pF  [CAP0402_0-75]
C87  0.1uF  [CAP0201_0-5]
C103  0.1uF  [CAP0201_0-5]
C106  0.1uF  [CAP0201_0-5]
C161  10pF  [CAP0402_0-75]
J13  HDR_1X6  [HDR_1X6_61300611121_S_T_8-6]
R42  1K  [RES0402_0-5]
R55  1K  [RES0402_0-5]
R56  1K  [RES0402_0-5]
R57  1K  [RES0402_0-5]
R58  1K  [RES0402_0-5]
R59  1K  [RES0402_0-5]
R60  1K  [RES0402_0-5]
R61  1K  [RES0402_0-5]
R62  1K  [RES0402_0-5]
R82  2.2K  [RES0402_0-5]
R88  2.2K  [RES0402_0-5]
R93  620E_1%  [RES0402_0-5]
R97  620E_1%  [RES0402_0-5]
R214  1K  [RES0402_0-5]
R215  1K  [RES0402_0-5]
R216  1K  [RES0402_0-5]
R217  1K  [RES0402_0-5]
R237  2.2K  [RES0402_0-5]
R238  2.2K  [RES0402_0-5]
R240  0E  [RES0402_0-5]
R244  0E  [RES0402_0-5]
R586  1K  [RES0402_0-5]
R587  1K  [RES0402_0-5]
U12  SN74CB3Q3125PWR  [TSSOP14_25-59_205X180_1-2]
U29  SN74LVC1G04DCKR  [SC70-5]
U32  SN74AVC8T245PWR  [TSSOP24_25-59_315X180_1-2]
sheet 15. SOC_QSPI_BOARD_ID_EEPROM
U18  XAM2434ASFGGAALX  [BGA293_19-68_440X440_1]  (sections A,B,C,D,E,F,G,H,I,J,K,L,M)

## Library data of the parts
C1 C2 C78 C79 = CAP: CAP CERAMIC 1uF 16V 20% X5R 0201; Chkd/date: MANIRAJA/300520; Crtd /date: ALVY/260520; Custom_Duty: 15%; Customs_HS_Code: 85322990; Distributor_name: DIGIKEY; Distributor_part_number: 490-18654-1-ND; Footprint Path: Y:\MIS_DATABASE\Library\ALTIUM_TOOL\PCB_FOOTPRINTS\Altium_Footprint_Lib.PcbLib; Height: 0.39MM; Library Path: Y:\MIS_DATABASE\Library\ALTIUM_TOOL\SCHEMATICS_PARTS\MS_DISCRETE_Library.schlib; Mfr_name: MURATA; Mfr_part_number: GRM033R61C105ME15D; Mistral Part No: 120018090038-R; Package: 0201; Part_type: CAPACITORS\CERAMIC; Project: QCS610_NANOSOM; RoHS: RoHS; Temperature: -55°C+85°C; Tolerance: 20%; Voltage: 16V; Wattage: NA; Weight: 0.33mg; Datasheet: Y:\MIS_DATABASE\DATASHEETS\CAPACITORS\GRM033R61C105ME15.PDF
C4 C29 C37 C87 C91 C103 C106 = CAP: CAP CERAMIC 0.1uF 16V 10% X5R 0201; Chkd/date: MANIRAJA/230118; Crtd /date: MANIRAJA/230118; Custom_Duty: 15%; Customs_HS_Code: 85322990; Distributor_name: DIGIKEY; Distributor_part_number: 490-14305-1-ND; Footprint Path: Y:\MIS_DATABASE\Library\ALTIUM_TOOL\PCB_FOOTPRINTS\Altium_Footprint_Lib.PcbLib; Height: 0.33MM; Library Path: Y:\MIS_DATABASE\Library\ALTIUM_TOOL\SCHEMATICS_PARTS\MS_DISCRETE_Library.schlib; Mfr_name: MURATA; Mfr_part_number: GRM033R61C104KE14D; Mistral Part No: 120009030072-R; Package: 0201; Part_type: CAPACITORS\CERAMIC; Project: TI_MAXIE_CPB; RoHS: RoHS; Temperature: -55°C+85°C; Tolerance: 10%; Voltage: 16V; Wattage: NA; Weight: 0.33mg; Datasheet: Y:\MIS_DATABASE\DATASHEETS\CAPACITORS\GRM033R61C104KE14.PDF
C80-C82 = CAP: CAP CERAMIC 2400pF 50V 5% C0G(NP0) 0603; Chkd/date: USMAN/231113; Crtd /date: USMAN/231113; Custom_Duty: 15%; Customs_HS_Code: 85322990; Distributor_name: DIGIKEY; Distributor_part_number: 490-3282-1-ND; Footprint Path: Y:\MIS_DATABASE\Library\ALTIUM_TOOL\PCB_FOOTPRINTS\Altium_Footprint_Lib.PcbLib; Height: 0.90MM; Library Path: Y:\MIS_DATABASE\Library\ALTIUM_TOOL\SCHEMATICS_PARTS\MS_DISCRETE_Library.schlib; Mfr_name: MURATA; Mfr_part_number: GRM1885C1H242JA01D; Mistral Part No: 120013110013-R; Package: 0603; Part_type: CAPACITORS\CERAMIC; Project: C-BAND_SYNTH; RoHS: RoHS; Temperature: -55°C+125°C; Tolerance: 5%; Voltage: 50V; Wattage: NA; Weight: 6.3mg; Datasheet: Y:\MIS_DATABASE\DATASHEETS\CAPACITORS\MURATA-GXX-SER_NOV17.PDF
D1 D2 D4 D5 = DIODE_TVS_DUAL: DIODE 1CH ESD PROTECTION FOR USB TYPE-C AND THUNDERBOLT3 X2SON2; Chkd/date: MANIRAJA/230920; Crtd /date: ALVY/230920; Custom_Duty: 15%; Customs_HS_Code: 85412900; Distributor_name: DIGIKEY; Distributor_part_number: 296-44484-1-ND; Footprint Path: Y:\MIS_DATABASE\Library\ALTIUM_TOOL\PCB_FOOTPRINTS\Altium_Footprint_Lib.PcbLib; Height: 0.32MM; Library Path: Y:\MIS_DATABASE\Library\ALTIUM_TOOL\SCHEMATICS_PARTS\MS_DISCRETE_Library.schlib; Mfr_name: TEXAS INSTRUMENTS; Mistral Part No: 130020090037-R; Package: X2SON2; Part_type: DIODE\TVS; Project: AM64X_SKEVM; RoHS: RoHS; Temperature: -40°C+125°C; Tolerance: NA; Voltage: NA; Wattage: NA; Weight: 0.2mg; Datasheet: Y:\MIS_DATABASE\DATASHEETS\DISCRETES\DIODES\TPD1E01B04.PDF
Q7 Q8 Q16 = MOSFET_CSD25310Q2: IC MOSFET P-CHANNEL WSON6; Chkd/date: VASANTHA/191215; Crtd /date: VASANTHA/191215; Custom_Duty: 15%; Customs_HS_Code: 85423100; Distributor_name: DIGIKEY; Distributor_part_number: 296-38915-1-ND; Height: 0.85MM; Mfr_name: TEXAS INSTRUMENTS; Mistral Part No: 142015120011-R; Package: WSON6; Part_type: ICS\POWER\MOSFET; Project: DUET BOARD; RoHS: RoHS; Temperature: -55°C+150°C; Tolerance: NA; Voltage: NA; Wattage: NA; Weight: NA; Datasheet: Y:\MIS_DATABASE\DATASHEETS\DISCRETES\TRANSISTORS_FETS\CSD25310Q2.PDF
R1 R42 R55-R62 R164 R170 R171 R214-R217 R586 R587 = RESISTOR: RES 1K 1/16W 5% 0402; Chkd/date: VASANTHA/120516; Crtd /date: VASANTHA/120516; Custom_Duty: 15%; Customs_HS_Code: 85332119; Distributor_name: DIGIKEY; Distributor_part_number: 311-1.0KJRCT-ND; Footprint Path: Y:\MIS_DATABASE\Library\ALTIUM_TOOL\PCB_FOOTPRINTS\Altium_Footprint_Lib.PcbLib; Height: 0.40MM; Library Path: Y:\MIS_DATABASE\Library\ALTIUM_TOOL\SCHEMATICS_PARTS\MS_DISCRETE_Library.schlib; Mfr_name: YAGEO AMERICA; Mfr_part_number: RC0402JR-071KL; Mistral Part No: 110010070006-R; Package: 0402; Part_type: RESISTORS\FIXED; Project: TMDXCSK368; RoHS: RoHS; Temperature: -55°C+155°C; Tolerance: 5%; Voltage: NA; Wattage: 1/16W; Weight: 0.65mg; Datasheet: Y:\MIS_DATABASE\DATASHEETS\RESISTORS\RCXXXXL-SER_MAR18.PDF
R2 R8 R240 R244 = RESISTOR: RES 0E 1/16W 5% 0402; Chkd/date: VASANTHA/291216; Crtd /date: CHAITHANYA/300911; Custom_Duty: 15%; Customs_HS_Code: 85332119; Distributor_name: DIGIKEY; Distributor_part_number: 311-0.0JRCT-ND; Footprint Path: Y:\MIS_DATABASE\Library\ALTIUM_TOOL\PCB_FOOTPRINTS\Altium_Footprint_Lib.PcbLib; Height: 0.40MM; Library Path: Y:\MIS_DATABASE\Library\ALTIUM_TOOL\SCHEMATICS_PARTS\MS_DISCRETE_Library.schlib; Mfr_name: YAGEO AMERICA; Mfr_part_number: RC0402JR-070RL; Mistral Part No: 110011090036-R; Package: 0402; Part_type: RESISTORS\FIXED; Project: VP-4000-PROCESSOR; RoHS: RoHS; Temperature: -55°C+155°C; Tolerance: 5%; Voltage: NA; Wattage: 1/16W; Weight: 0.65mg; Datasheet: Y:\MIS_DATABASE\DATASHEETS\RESISTORS\RCXXXXL-SER_MAR18.PDF
R3 R4 R9 R11 R15 R188 = RESISTOR: RES 10K 1/16W 5% 0402; Chkd/date: VASANTHA/061216; Crtd /date: MAZHAR/230805; Custom_Duty: 15%; Customs_HS_Code: 85332119; Distributor_name: DIGIKEY; Distributor_part_number: 311-10KJRCT-ND; Footprint Path: Y:\MIS_DATABASE\Library\ALTIUM_TOOL\PCB_FOOTPRINTS\Altium_Footprint_Lib.PcbLib; Height: 0.40MM; Library Path: Y:\MIS_DATABASE\Library\ALTIUM_TOOL\SCHEMATICS_PARTS\MS_DISCRETE_Library.schlib; Mfr_name: YAGEO AMERICA; Mfr_part_number: RC0402JR-0710KL; Mistral Part No: 110011060021-R; Package: 0402; Part_type: RESISTORS\FIXED; Project: HSE; RoHS: RoHS; Temperature: -55°C+155°C; Tolerance: 5%; Voltage: NA; Wattage: 1/16W; Weight: 0.65mg; Datasheet: Y:\MIS_DATABASE\DATASHEETS\RESISTORS\RCXXXXL-SER_MAR18.PDF
R6 = RESISTOR: RES 12.7K 1/10W 1% 0402; Chkd/date: MANIRAJA/280519; Crtd /date: ALVY/270519; Custom_Duty: 15%; Customs_HS_Code: 85332119; Distributor_name: DIGIKEY; Distributor_part_number: P12.7KLCT-ND; Footprint Path: Y:\MIS_DATABASE\Library\ALTIUM_TOOL\PCB_FOOTPRINTS\Altium_Footprint_Lib.PcbLib; Height: 0.40MM; Library Path: Y:\MIS_DATABASE\Library\ALTIUM_TOOL\SCHEMATICS_PARTS\MS_DISCRETE_Library.schlib; Mfr_name: PANASONIC-ECG; Mfr_part_number: ERJ-2RKF1272X; Mistral Part No: 110019050035-R; Package: 0402; Part_type: RESISTORS\FIXED; Project: BRUKER_SD820_COMMONDO; RoHS: RoHS; Temperature: -55°C+155°C; Tolerance: 1%; Voltage: NA; Wattage: 1/10W; Weight: 0.8mg; Datasheet: Y:\MIS_DATABASE\DATASHEETS\RESISTORS\PAN-ERJSER_NOV17.PDF
R175 = RESISTOR: RES 88.7K 1/16W 1% 0402; Chkd/date: MANIRAJA/130519; Crtd /date: ALVY/100519; Custom_Duty: 15%; Customs_HS_Code: 85332119; Distributor_name: DIGIKEY; Distributor_part_number: 311-88.7KLRCT-ND; Footprint Path: Y:\MIS_DATABASE\Library\ALTIUM_TOOL\PCB_FOOTPRINTS\Altium_Footprint_Lib.PcbLib; Height: 0.40MM; Library Path: Y:\MIS_DATABASE\Library\ALTIUM_TOOL\SCHEMATICS_PARTS\MS_DISCRETE_Library.schlib; Mfr_name: YAGEO AMERICA; Mfr_part_number: RC0402FR-0788K7L; Mistral Part No: 110011080015-R; Package: 0402; Part_type: RESISTORS\FIXED; Project: BRUKER_SD820_COMMONDO; RoHS: RoHS; Temperature: -55°C+155°C; Tolerance: 1%; Voltage: NA; Wattage: 1/16W; Weight: 0.65mg; Datasheet: Y:\MIS_DATABASE\DATASHEETS\RESISTORS\RCXXXXL-SER_MAR18.PDF
R176 R201 = RESISTOR: RES 100K 1/16W 1% 0402; Chkd/date: MANIRAJA/110917; Crtd /date: MANIRAJA/110917; Custom_Duty: 15%; Customs_HS_Code: 85332119; Distributor_name: DIGIKEY; Distributor_part_number: 311-100KLRCT-ND; Footprint Path: Y:\MIS_DATABASE\Library\ALTIUM_TOOL\PCB_FOOTPRINTS\Altium_Footprint_Lib.PcbLib; Height: 0.40MM; Library Path: Y:\MIS_DATABASE\Library\ALTIUM_TOOL\SCHEMATICS_PARTS\MS_DISCRETE_Library.schlib; Mfr_name: YAGEO AMERICA; Mfr_part_number: RC0402FR-07100KL; Mistral Part No: 110014060043-R; Package: 0402; Part_type: RESISTORS\FIXED; Project: CRADE RF CARD; RoHS: RoHS; Temperature: -55°C+155°C; Tolerance: 1%; Voltage: NA; Wattage: 1/16W; Weight: 0.65mg; Datasheet: Y:\MIS_DATABASE\DATASHEETS\RESISTORS\RCXXXXL-SER_MAR18.PDF
R195 = RESISTOR: RES 14.7K 1/10W 1% 0402; Chkd/date: SUHAS/270910; Crtd /date: MAZHAR/241109; Custom_Duty: 15%; Customs_HS_Code: 85332119; Distributor_name: DIGIKEY; Distributor_part_number: P14.7KLCT-ND; Footprint Path: Y:\MIS_DATABASE\Library\ALTIUM_TOOL\PCB_FOOTPRINTS\Altium_Footprint_Lib.PcbLib; Height: 0.40MM; Library Path: Y:\MIS_DATABASE\Library\ALTIUM_TOOL\SCHEMATICS_PARTS\MS_DISCRETE_Library.schlib; Mfr_name: PANASONIC-ECG; Mfr_part_number: ERJ-2RKF1472X; Mistral Part No: 110009110010-R; Package: 0402; Part_type: RESISTORS\FIXED; Project: GOLDEN-I; RoHS: RoHS; Temperature: -55°C+155°C; Tolerance: 1%; Voltage: NA; Wattage: 1/10W; Weight: 0.8mg; Datasheet: Y:\MIS_DATABASE\DATASHEETS\RESISTORS\PAN-ERJSER_NOV17.PDF
R198 = RESISTOR: RES 16.9K 1/16W 1% 0402; Chkd/date: MANIRAJA/280920; Crtd /date: ALVY/250920; Custom_Duty: 15%; Customs_HS_Code: 85332119; Distributor_name: DIGIKEY; Distributor_part_number: YAG3003CT-ND; Footprint Path: Y:\MIS_DATABASE\Library\ALTIUM_TOOL\PCB_FOOTPRINTS\Altium_Footprint_Lib.PcbLib; Height: 0.40MM; Library Path: Y:\MIS_DATABASE\Library\ALTIUM_TOOL\SCHEMATICS_PARTS\MS_DISCRETE_Library.schlib; Mfr_name: YAGEO AMERICA; Mfr_part_number: RC0402FR-0716K9L; Mistral Part No: 110020090010-R; Package: 0402; Part_type: RESISTORS\FIXED; Project: TI_J7ES_CP; RoHS: RoHS; Temperature: -55°C+155°C; Tolerance: 1%; Voltage: NA; Wattage: 1/16W; Weight: 12mg; Datasheet: Y:\MIS_DATABASE\DATASHEETS\RESISTORS\RCXXXXL-SER_MAR18.PDF
R199 = RESISTOR: RES 5.23K 1/16W 1% 0402; Chkd/date: JEBRAN/110815; Crtd /date: JEBRAN/110815; Custom_Duty: 15%; Customs_HS_Code: 85332119; Distributor_name: DIGIKEY; Distributor_part_number: 541-5.23KLCT-ND; Footprint Path: Y:\MIS_DATABASE\Library\ALTIUM_TOOL\PCB_FOOTPRINTS\Altium_Footprint_Lib.PcbLib; Height: 0.40MM; Library Path: Y:\MIS_DATABASE\Library\ALTIUM_TOOL\SCHEMATICS_PARTS\MS_DISCRETE_Library.schlib; Mfr_name: VISHAY; Mfr_part_number: CRCW04025K23FKED; Mistral Part No: 110015080018-R; Package: 0402; Part_type: RESISTORS\FIXED; Project: OCTASIC_3000; RoHS: RoHS; Temperature: -55°C+155°C; Tolerance: 1%; Voltage: NA; Wattage: 1/16W; Weight: 0.65mg; Datasheet: Y:\MIS_DATABASE\DATASHEETS\RESISTORS\CRCW0603.PDF
SW1-SW3 SW5 = SW4_EVQP: SWITCH TACTILE SPST RT SMD; Chkd/date: MANIRAJA/051020; Crtd /date: ALVY/011020; Custom_Duty: 24%; Customs_HS_Code: 85369090; Distributor_name: DIGIKEY; Distributor_part_number: 732-7059-1-ND; Footprint Path: Y:\MIS_DATABASE\Library\ALTIUM_TOOL\PCB_FOOTPRINTS\Altium_Footprint_Lib.PcbLib; Height: 1.65MM; Library Path: Y:\MIS_DATABASE\Library\ALTIUM_TOOL\SCHEMATICS_PARTS\MS_SWITCH_Library.schlib; Mfr_name: WURTH ELECTRONICS; Mistral Part No: 130020100002-R; Package: SMD; Part_type: ELECTRO-MECHANICAL\SWITCH; Project: AM64X_SKEVM; RoHS: RoHS; Temperature: -40°C+85°C; Tolerance: NA; Voltage: NA; Wattage: NA; Weight: 50mg; Datasheet: Y:\MIS_DATABASE\DATASHEETS\MISC\SWITCHES\436331045822.PDF
TP1 TP12 TP19 TP24 = TESTPOINT: TESTPOINT CIR 20 SMD; Chkd/date: SHREESHAIL/171006; Crtd /date: MAZHAR/171006; Custom_Duty: NA; Customs_HS_Code: NA; Distributor_name: NA; Distributor_part_number: NA; Footprint Path: Y:\MIS_DATABASE\Library\ALTIUM_TOOL\PCB_FOOTPRINTS\Altium_Footprint_Lib.PcbLib; Height: NA; Library Path: Y:\MIS_DATABASE\Library\ALTIUM_TOOL\SCHEMATICS_PARTS\MS_DISCRETE_Library.schlib; MECHANICAL 3D STEP FILE: NA; Mfr_name: LOCAL; Mistral Part No: NA; Package: SMD; Project: BT MODULE_CSRBC04; RoHS: NA; Temperature: NA; Tolerance: NA; Voltage: NA; Wattage: NA; Weight: NA; Datasheet: NA
U1 = SN74LVC1G11DCKR_SC70-6: IC SINGLE 3-INPUT POSITIVE-AND GATE SC70-6; Chkd/date: SHREESHAIL/220506; Crtd /date: MAZHAR/150506; Custom_Duty: 15%; Customs_HS_Code: 85423100; Distributor_name: DIGIKEY; Distributor_part_number: 296-18066-1-ND; Height: 1.10MM; Mfr_name: TEXAS INSTRUMENTS; Mistral Part No: 141009030230-R; Part_type: ICS\DIGITAL\GATES; Project: VOCERA; RoHS: Sb/ Br FREE; Datasheet: Y:\MIS_DATABASE\DATASHEETS\ICS\DIGITAL\GATES\SN74LVC1G.PDF
U13 = SN74LVC3G17DCUR_VSSOP8: IC TRIPLE SCHMITT-TRIGGER BUFFER VSSOP8; Chkd/date: MANIRAJA/280917; Crtd /date: MANIRAJA/280917; Custom_Duty: 15%; Customs_HS_Code: 85423100; Distributor_name: DIGIKEY; Distributor_part_number: 296-18818-1-ND; Height: 0.90MM; Mfr_name: TEXAS INSTRUMENTS; Mistral Part No: 141017090019-R; Package: VSSOP8; Part_type: ICS\DIGITAL\COMBINATIONAL; Project: TI_MAXIE_CPB; RoHS: RoHS; Temperature: -40°C+125°C; Tolerance: NA; Voltage: NA; Wattage: NA; Weight: 9.6mg; Datasheet: Y:\MIS_DATABASE\DATASHEETS\ICS\DIGITAL\COMBINATIONAL\SN74LVC3G17.PDF
U27 = TPS386000RGPR_QFN20: IC QUAD SUPPLY SUPERVISORS WITH ADJ DELAY & WATCHDOG TIMER QFN20; Chkd/date: VASANTHA/230117; Crtd /date: MANIRAJA/230117; Custom_Duty: 15%; Customs_HS_Code: 85423100; Distributor_name: DIGIKEY; Distributor_part_number: 296-39392-1-ND; Height: 1.00MM; Mfr_name: TEXAS INSTRUMENTS; Mistral Part No: 142017010013-R; Package: QFN20; Part_type: ICS\POWER; Project: CRADE-CONTROLLER CARD; RoHS: RoHS; Temperature: -40°C+125°C; Tolerance: NA; Voltage: NA; Wattage: NA; Weight: 70mg; Datasheet: Y:\MIS_DATABASE\DATASHEETS\ICS\POWER\TPS3860.PDF
C47 C161 = CAP: CAP CERAMIC 10pF 16V 5% C0G(NP0) 0402; Chkd/date: MANIRAJA/100918; Crtd /date: ALVY/100918; Custom_Duty: 15%; Customs_HS_Code: 85322990; Distributor_name: DIGIKEY; Distributor_part_number: 732-7441-1-ND; Footprint Path: Y:\MIS_DATABASE\Library\ALTIUM_TOOL\PCB_FOOTPRINTS\Altium_Footprint_Lib.PcbLib; Height: 0.55MM; Library Path: Y:\MIS_DATABASE\Library\ALTIUM_TOOL\SCHEMATICS_PARTS\MS_DISCRETE_Library.schlib; Mfr_name: WURTH ELECTRONICS; Mfr_part_number: 885012005025; Mistral Part No: 120018030015-R; Package: 0402; Part_type: CAPACITORS\CERAMIC; Project: SMART-M_SCRIPTALK_PB; RoHS: RoHS; Temperature: -55°C+125°C; Tolerance: 5%; Voltage: 16V; Wattage: NA; Weight: 0.65mg; Datasheet: Y:\MIS_DATABASE\DATASHEETS\CAPACITORS\885012005025.PDF
J13 = HEADER_6X1: CON HDR 1X6 2.54MM PITCH ST TH; Chkd/date: MANIRAJA/161219; Crtd /date: MANIRAJA/161219; Custom_Duty: 24%; Customs_HS_Code: 85369090; Distributor_name: DIGIKEY; Distributor_part_number: 732-5319-ND; Footprint Path: Y:\MIS_DATABASE\Library\ALTIUM_TOOL\PCB_FOOTPRINTS\Altium_Footprint_Lib.PcbLib; Height: 8.54MM; Library Path: Y:\MIS_DATABASE\Library\ALTIUM_TOOL\SCHEMATICS_PARTS\MS_CONNECTOR_Library.schlib; Mfr_name: WURTH ELECTRONICS; Mfr_part_number: 61300611121; Mistral Part No: 150019120017-R; Package: THRU-HOLE; Part_type: CONNECTOR\HEADERS; Project: SD820_NANOSOM_TESTJIG; RoHS: RoHS; Temperature: -40°C+105°C; Tolerance: NA; Voltage: NA; Wattage: NA; Weight: 342.4mg; Datasheet: Y:\MIS_DATABASE\DATASHEETS\CONNECTORS\6130XXX.PDF
R82 R88 R237 R238 = RESISTOR: RES 2.2K 1/16W 5% 0402; Chkd/date: VASANTHA/061216; Crtd /date: BAVISH/021210; Custom_Duty: 15%; Customs_HS_Code: 85332119; Distributor_name: DIGIKEY; Distributor_part_number: 311-2.2KJRCT-ND; Footprint Path: Y:\MIS_DATABASE\Library\ALTIUM_TOOL\PCB_FOOTPRINTS\Altium_Footprint_Lib.PcbLib; Height: 0.40MM; Library Path: Y:\MIS_DATABASE\Library\ALTIUM_TOOL\SCHEMATICS_PARTS\MS_DISCRETE_Library.schlib; Mfr_name: YAGEO AMERICA; Mfr_part_number: RC0402JR-072K2L; Mistral Part No: 110010120018-R; Package: 0402; Part_type: RESISTORS\FIXED; Project: TE4; RoHS: RoHS; Temperature: -55°C+155°C; Tolerance: 5%; Voltage: NA; Wattage: 1/16W; Weight: 0.65mg; Datasheet: Y:\MIS_DATABASE\DATASHEETS\RESISTORS\RCXXXXL-SER_MAR18.PDF
R93 R97 = RESISTOR: RES 620E 1/16W 1% 0402; Chkd/date: ALVY/091220; Crtd /date: MANIRAJA/091220; Custom_Duty: 15%; Customs_HS_Code: 85332119; Distributor_name: DIGIKEY; Distributor_part_number: 311-620LRCT-ND; Footprint Path: Y:\MIS_DATABASE\Library\ALTIUM_TOOL\PCB_FOOTPRINTS\Altium_Footprint_Lib.PcbLib; Height: 0.40MM; Library Path: Y:\MIS_DATABASE\Library\ALTIUM_TOOL\SCHEMATICS_PARTS\MS_DISCRETE_Library.schlib; Mfr_name: YAGEO AMERICA; Mfr_part_number: RC0402FR-07620RL; Mistral Part No: 110020120009-R; Package: 0402; Part_type: RESISTORS\FIXED; Project: TI_AM243x LP EVM; RoHS: RoHS; Temperature: -55°C+155°C; Tolerance: 1%; Voltage: NA; Wattage: 1/16W; Weight: 0.65mg; Datasheet: Y:\MIS_DATABASE\DATASHEETS\RESISTORS\RCXXXXL-SER_MAR18.PDF
U12 = SN74CBTLV3125PWR_TSSOP14: IC 2.5/3.3V QUADRUPLE HIGH-BANDWIDTH FET BUS SWITCH TSSOP14; Chkd/date: MANIRAJA/241018; Crtd /date: ALVY/241018; Custom_Duty: 15%; Customs_HS_Code: 85423100; Distributor_name: DIGIKEY; Distributor_part_number: 296-16804-1-ND; Footprint Path: Y:\MIS_DATABASE\Library\ALTIUM_TOOL\PCB_FOOTPRINTS\Altium_Footprint_Lib.PcbLib; Height: 1.20MM; Library Path: Y:\MIS_DATABASE\Library\ALTIUM_TOOL\SCHEMATICS_PARTS\MS_COMBINATIONAL_Library.schlib; Mfr_name: TEXAS INSTRUMENTS; Mistral Part No: 141018100021-R; Package: TSSOP14; Part_type: ICS\DIGITAL\COMBINATIONAL; Project: TI_J7ES_EVM_CP; RoHS: RoHS; Temperature: -40°C+85°C; Tolerance: NA; Voltage: NA; Wattage: NA; Weight: 57.2mg; Datasheet: Y:\MIS_DATABASE\DATASHEETS\ICS\DIGITAL\COMBINATIONAL\SN74CB3Q3125.PDF
U29 = SN74LVC1G04DCKR_SC70-5: IC SINGLE INVERTER GATE SC70-5; Chkd/date: SUHAS/221010; Crtd /date: USMAN/150709; Custom_Duty: 15%; Customs_HS_Code: 85423100; Distributor_name: DIGIKEY; Distributor_part_number: 296-11600-1-ND; Height: 1.10MM; Mfr_name: TEXAS INSTRUMENTS; Mistral Part No: 141009070007-R; Part_type: ICS\DIGITAL\GATES; Project: BUG_BASE-II; RoHS: Sb/ Br FREE; Temperature: -40°C+85°C; Datasheet: Y:\MIS_DATABASE\DATASHEETS\ICS\DIGITAL\GATES\SN74LVC1G04-1.PDF
U32 = SN74AVC8T245PWR_TSSOP24: IC 8-BIT DUAL-SUPPLY BUS TRANSCEIVER TSSOP24; Chkd/date: MANIRAJA/040917; Crtd /date: USMAN/040509; Custom_Duty: 15%; Customs_HS_Code: 85423100; Distributor_name: DIGIKEY; Distributor_part_number: 296-19100-1-ND; Height: 1.20MM; Mfr_name: TEXAS INSTRUMENTS; Mistral Part No: 143009060004-R; Package: TSSOP24; Part_type: ICS\TELECOM\TRANSCEIVER; Project: STORM2; RoHS: RoHS; Temperature: -40°C+85°C; Tolerance: NA; Voltage: NA; Wattage: NA; Weight: 89.5mg; Datasheet: Y:\MIS_DATABASE\DATASHEETS\ICS\DIGITAL\BUSTRANSCEIVER\SN74AVC8T245.PDF
U18 = AM243X_SOC_LP_EVM_BGA293: IC AM243x SoC_LP_EVM MICROPROCESSOR BGA293; Chkd/date: MANIRAJA/131120; Crtd /date: ALVY/121120; Custom_Duty: 15%; Customs_HS_Code: 85423100; Distributor_name: NA; Distributor_part_number: NA; Footprint Path: Y:\MIS_DATABASE\Library\ALTIUM_TOOL\PCB_FOOTPRINTS\Altium_Footprint_Lib.PcbLib; Height: 1.00MM; Library Path: Y:\MIS_DATABASE\Library\ALTIUM_TOOL\SCHEMATICS_PARTS\MS_MICROPROCESSOR_Library.schlib; Library Ref: AM243x SoC_LP_EVM_BGA293; Mfr_name: TEXAS INSTRUMENTS; Mistral Part No: 141220110003; Package: BGA293; Part_type: ICS\DIGITAL\MICROPROCESSOR; Project: TI_AM243x LP EVM; RoHS: NA; Temperature: NA; Tolerance: NA; Voltage: NA; Wattage: NA; Weight: NA; Datasheet: Y:\MIS_DATABASE\DATASHEETS\ICS\DIGITAL\MICROCONTROLLER\AM243x SoC-FP.PDF

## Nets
DGND: C1.2 C2.2 C4.2 C29.2 C37.2 C47.2 C78.2 C79.2 C80.2 C81.2 C82.2 C87.2 C91.2 C103.2 C106.2 C161.2 D1.2(ANODE) D2.2(ANODE) D4.2(ANODE) D5.2(ANODE) J13.1 Q7.4(D1) Q7.7(D2) Q8.4(D1) Q8.7(D2) Q16.4(D1) Q16.7(D2) R9.1 R175.1 R195.2 R199.2 SW1.2 SW1.4 SW2.2 SW2.4 SW3.2 SW3.4 SW5.2 SW5.4 U1.2(GND) U12.1(~{1OE}) U12.4(~{2OE}) U12.7(GND) U12.10(~{3OE}) U12.13(~{4OE}) U13.4(GND) U27.12(GND) U27.21(EP) U29.3(GND) U32.2(DIR) U32.8(A6) U32.9(A7) U32.10(A8) U32.11(GND1) U32.12(GND2) U32.13(GND3) U32.14(B8) U32.15(B7) U32.16(B6) ; also on sheet 12 13 14 15 16 17 18 19 20 21 22 23 24 25 26 27 28
VDD_1V8: R198.1 ; also on sheet 12 25 28
VDD_1V8_CT: C80.1 U27.5(CT1)
VDD_1V8_SENSE: R198.2 R199.1 U27.10(SENSE1)
VDD_CORE_0V85: R176.2 ; also on sheet 24 25 27
VDD_CORE_0V85_H_SENSE: R6.1 R175.2 U27.6(SENSE4H)
VDD_CORE_0V85_L_SENSE: R6.2 R176.1 U27.7(SENSE4L)
VDDA_1V8: C4.1 R15.2 U1.5(VCC) ; also on sheet 25
BOOTMODE0: R55.2 ; also on sheet 21
BOOTMODE0_R: R55.1 U18.R21(GPMC0_AD0) U32.3(A1)
BOOTMODE1: R56.2 ; also on sheet 21
BOOTMODE2: R215.2 ; also on sheet 21
BOOTMODE2_R: R215.1 U18.T19(GPMC0_AD2) U32.7(A5)
BOOTMODE3: R42.2 ; also on sheet 21
BOOTMODE4: R59.2 ; also on sheet 21
BOOTMODE5: R57.2 ; also on sheet 21
BOOTMODE6: R217.2 ; also on sheet 21
BOOTMODE7: R216.2 ; also on sheet 21
BOOTMODE8: R214.2 ; also on sheet 21
BOOTMODE8_R: R214.1 U18.U18(GPMC0_AD8) U32.4(A2)
BOOTMODE9: R58.2 ; also on sheet 21
BOOTMODE9_R: R58.1 U18.U20(GPMC0_AD9) U32.5(A3)
BOOTMODE10: R60.2 ; also on sheet 21
BOOTMODE10_R: R60.1 U18.V20(GPMC0_AD10) U32.6(A4)
BOOTMODE11: R61.2 ; also on sheet 21
BOOTMODE12: R62.2 ; also on sheet 21
BOOTMODE14: R586.2 ; also on sheet 21
BOOTMODE15: R587.2 ; also on sheet 21
BP_CONN_1_PORz: R8.1 ; also on sheet 19
BP_CONN_2_PORz: R2.1 ; also on sheet 19
BUFF_ENABLE: U29.4(Y) U32.22(~{OE})
CORE_0V85_CT: C82.1 U27.2(CT4)
CPSW_RGMII1_RD0: U18.T5(PRG0_PRU1_GPO7) ; also on sheet 16
CPSW_RGMII1_RD1: U18.R2(PRG0_PRU1_GPO9) ; also on sheet 16
CPSW_RGMII1_RD2: U18.U2(PRG0_PRU1_GPO10) ; also on sheet 16
CPSW_RGMII1_RD3: U18.T1(PRG0_PRU1_GPO17) ; also on sheet 16
CPSW_RGMII1_RX_CTL: U18.Y3(PRG0_PRU0_GPO9) ; also on sheet 16
CPSW_RGMII1_RXC: U18.U1(PRG0_PRU0_GPO10) ; also on sheet 16
Debounce_MCU_RESETz: C1.1 D1.1(CATHODE) R1.1 SW2.1 SW2.3 U13.1(1A)
Debounce_SoC_RESET_REQz: C2.1 D2.1(CATHODE) Q7.1(S1) Q7.2(S2) Q7.5(S3) Q7.6(S4) Q7.8(S5) R170.1 SW3.1 SW3.3 U13.6(3A)
Debounce_USER_INTn: C78.1 D4.1(CATHODE) Q16.1(S1) Q16.2(S2) Q16.5(S3) Q16.6(S4) Q16.8(S5) R164.1 SW5.1 SW5.3 U13.3(2A)
EHRPWM0_A: R42.1 U18.V21(GPMC0_AD3) ; also on sheet 19
EHRPWM0_B: R59.1 U18.U21(GPMC0_AD4) ; also on sheet 19
EHRPWM0_TZn_IN0: U32.17(B5) ; also on sheet 19
EHRPWM1_A: R57.1 U18.T20(GPMC0_AD5) ; also on sheet 19
EHRPWM1_B: R217.1 U18.T18(GPMC0_AD6) ; also on sheet 19
eQEP1_A_LS: U18.L2(PRG0_PRU1_GPO3) ; also on sheet 13
eQEP1_B_LS: U18.L3(PRG0_PRU1_GPO4) ; also on sheet 13
eQEP1_I_LS: U18.R5(PRG0_PRU1_GPO14) ; also on sheet 13
eQEP2_A_LS: U18.B14(MCAN1_TX) ; also on sheet 13
eQEP2_B_LS: R244.2 ; also on sheet 13
FSI/BP_MUX_SEL: U18.Y19(GPMC0_AD13) ; also on sheet 13
FSI_RX0_D1: U32.18(B4) ; also on sheet 14
FSI_RX0CLK_PWM2A: U32.20(B2) ; also on sheet 13
FSI_RX0D0_PWM2B: U32.19(B3) ; also on sheet 13
FSI_TX0_CLK: U18.P21(GPMC0_BE1N) ; also on sheet 14
FSI_TX0_D0: R586.1 U18.Y18(GPMC0_AD14) ; also on sheet 14
FSI_TX0_D1: R587.1 U18.AA19(GPMC0_AD15) ; also on sheet 14
GPIO1_0: U18.J3(PRG0_PRU0_GPO0) ; also on sheet 19
GPIO1_1: U18.J4(PRG0_PRU0_GPO1) ; also on sheet 19
GPIO1_2: U18.G1(PRG0_PRU0_GPO2) ; also on sheet 19
GPIO1_3: U18.H1(PRG0_PRU0_GPO3) ; also on sheet 19
GPIO1_4: U18.K2(PRG0_PRU0_GPO4) ; also on sheet 19
GPIO1_5: U18.F2(PRG0_PRU0_GPO5) ; also on sheet 19
GPIO1_6: U18.H2(PRG0_PRU0_GPO6) ; also on sheet 19
GPIO1_8: U18.H5(PRG0_PRU0_GPO8) ; also on sheet 19
GPIO1_12: U18.K1(PRG0_PRU0_GPO12) ; also on sheet 19
GPIO1_18: U18.K4(PRG0_PRU0_GPO18) ; also on sheet 19
GPIO1_19: U18.G2(PRG0_PRU0_GPO19) ; also on sheet 19
GPIO1_20: U18.L5(PRG0_PRU1_GPO0) ; also on sheet 19
GPIO1_21: U18.J2(PRG0_PRU1_GPO1) ; also on sheet 19
GPIO1_22: U18.M2(PRG0_PRU1_GPO2) ; also on sheet 19
GPIO1_26: U18.F5(PRG0_PRU1_GPO6) ; also on sheet 19
GPIO1_31: U18.P1(PRG0_PRU1_GPO11) ; also on sheet 19
GPIO1_32: U18.P2(PRG0_PRU1_GPO12) ; also on sheet 19
GPIO1_33: U18.T4(PRG0_PRU1_GPO13) ; also on sheet 19
GPIO1_35: U18.M4(PRG0_PRU1_GPO15) ; also on sheet 19
GPIO1_36: U18.T3(PRG0_PRU1_GPO16) ; also on sheet 19
GPIO1_40: U18.E4(PRG0_MDIO0_MDIO) ; also on sheet 19
GPIO1_41: U18.D2(PRG0_MDIO0_MDC) ; also on sheet 19
MAIN_UART0_RXD: U18.B10(UART0_RXD) ; also on sheet 22
MAIN_UART0_TXD: U18.B11(UART0_TXD) ; also on sheet 22
MAIN_UART1_CTS#: U12.11(4B) U18.C11(UART1_CTSN)
MAIN_UART1_RTS#: U12.5(2A) U18.A11(UART1_RTSN)
MAIN_UART1_RXD: U12.8(3B) U18.B12(UART1_RXD)
MAIN_UART1_TXD: U12.2(1A) U18.A12(UART1_TXD)
MAIN_UART2_RXD: U32.21(B1) ; also on sheet 19
MAIN_UART2_TXD: R56.1 U18.R20(GPMC0_AD1) ; also on sheet 19
MAIN_UART4_RXD: U18.L1(PRG0_PRU0_GPO11) ; also on sheet 19
MAIN_UART4_TXD: U18.E2(PRG0_PRU0_GPO7) ; also on sheet 19
MCAN0_RX_MUX: U18.A14(MCAN0_RX) ; also on sheet 13
MCAN0_STB: U18.E3(PRG0_PRU1_GPO5) ; also on sheet 14
MCAN0_TX_eQEP2_I: U18.B13(MCAN0_TX) ; also on sheet 13
MCAN/eQEP_MUX_SEL: U18.F4(PRG0_PRU1_GPO8) ; also on sheet 13
MCU_PORz: TP1.1(TP) U1.4(Y) ; also on sheet 12
MCU_RESETz: TP19.1(TP) U13.7(1Y) ; also on sheet 12
OBSCLK0: R240.2 ; also on sheet 18
PORZ_OUT: U29.2(A) ; also on sheet 12 15 17 18 21
R_BP_CONN_1_PORz: R4.1 R8.2 U1.3(B)
R_BP_CONN_2_PORz: R2.2 R3.1 U1.6(C)
SENCE3_IP: R188.2 U27.8(SENSE3)
SoC_I2C0_SCL: R93.1 R237.2 ; also on sheet 15 19 23
SoC_I2C0_SCL_RC: C47.1 R93.2 U18.B16(I2C0_SCL)
SoC_I2C0_SDA: R97.1 R238.2 ; also on sheet 15 19 23
SoC_I2C0_SDA_RC: C161.1 R97.2 U18.B15(I2C0_SDA)
SoC_I2C1_SCL: R88.2 U18.A17(I2C1_SCL) ; also on sheet 19 20
SoC_I2C1_SDA: R82.2 U18.B18(I2C1_SDA) ; also on sheet 19 20
SoC_RESET_REQz: TP24.1(TP) U13.2(3Y) ; also on sheet 12
SPI0_CLK: U18.B8(SPI0_CLK) ; also on sheet 19
SPI0_CS1: U18.B7(SPI0_CS1) ; also on sheet 19
SPI0_D0: U18.A8(SPI0_D0) ; also on sheet 19
SPI0_D1: U18.C9(SPI0_D1) ; also on sheet 19
SPI3_CLK: U18.N3(PRG0_PRU0_GPO16) ; also on sheet 19
SPI3_CS0: U18.E1(PRG0_PRU0_GPO17) ; also on sheet 19
SPI3_CS1: U18.N4(PRG0_PRU0_GPO15) ; also on sheet 19
SPI3_D0: U18.N1(PRG0_PRU0_GPO13) ; also on sheet 19
SPI3_D1: U18.N2(PRG0_PRU0_GPO14) ; also on sheet 19
SYNC1_OUT: U18.A18(EXT_REFCLK1) ; also on sheet 19
TA_PORZn: Q8.3(G) ; also on sheet 20
TA_SOC_INTn: Q16.3(G) ; also on sheet 20
TA_WARMRESETn: Q7.3(G) ; also on sheet 20
TEST_LED1_GREEN: R216.1 U18.U19(GPMC0_AD7) ; also on sheet 23
TEST_LED2_RED: U18.A9(UART0_RTSN) ; also on sheet 23
TEST_LED3_RED: U18.D1(PRG0_PRU1_GPO18) ; also on sheet 23
TEST_LED4_GREEN: U18.F3(PRG0_PRU1_GPO19) ; also on sheet 23
UART1_HDR_CTS#: J13.2 U12.6(2B)
UART1_HDR_RTS#: J13.6 U12.12(4A)
UART1_HDR_RXD: J13.5 U12.3(1B)
UART1_HDR_TXD: J13.4 U12.9(3A)
USER_INTn: TP12.1(TP) U13.5(2Y) U18.B9(UART0_CTSN)
USER_LED1: R61.1 U18.W20(GPMC0_AD11) ; also on sheet 13
USER_LED2: R62.1 U18.Y20(GPMC0_AD12) ; also on sheet 13
VMON_MRn: C79.1 D5.1(CATHODE) Q8.1(S1) Q8.2(S2) Q8.5(S3) Q8.6(S4) Q8.8(S5) R171.1 SW1.1 SW1.3 U27.1(~{MR})
VSYS_3V3: C29.1 C37.1 C87.1 C103.1 C106.1 R1.2 R3.2 R4.2 R82.1 R88.1 R164.2 R170.2 R201.2 R237.1 R238.1 U12.14(VCC) U13.8(VCC) U29.5(VCC) U32.1(VCCA) U32.23(VCCB1) U32.24(VCCB2) ; also on sheet 12 13 14 15 16 17 18 19 20 21 22 23 24 25 27 28
VSYS_3V3_CT: C81.1 U27.4(CT2)
VSYS_3V3_SENSE: R195.1 R201.1 U27.9(SENSE2)
VSYS_5V0: C91.1 R11.1 R171.2 R188.1 U27.14(VDD) ; also on sheet 13 14 19 20 25 26 27 28
WDI: R9.2 U27.20(WDI)
WDO: R11.2 U27.19(WDO)
N30339679: R15.1 U1.1(A) U27.15(~{RESET1}) U27.16(~{RESET2}) U27.18(~{RESET4})
N30900913: R240.1 R244.1 U18.A15(MCAN1_RX)

Not connected (* = marked no-connect by the designer): J13 3*; U18 H11(RSVD)*; U27 3(CT3)* 11(NC)* 13(VREF)* 17(~{RESET3})*; U29 1(NC)*

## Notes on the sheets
sheet 1
- AM243x LAUNCH PAD
- TABLE OF CONTENTS
- PAGE
- CONTENTS
- 01
- TABLE OF CONTENTS
- 02
- REVISION HISTORY
- 03
- BLOCK DIAGRAM
- REV
- E2
- 04
- POWER TREE
- VER
- 1.0
- 05
- POWER ON SEQUENCE
- 06
- RESET ARCHITECTURE
- 07
- GPIO MAPPING TABLE
- 08
- I2C TREE
- 09
- BOOSTERPACK CONNECTOR PINOUTS
- 10
- RESET INPUTs
- 11
- SOC1
- 12
- SOC2
- 13
- MCAN_eQEP_FSI_MUX & USER LEDs
- 14
- CAN_eQEP_FSI_HEADERs & CLOCK BUFFER
- 15
- QSPI_BOARD_ID_EEPROM
- 16
- ETHERNET DATA MUX & ADC INPUTS
- 17
- PRG/CPSW RGMII1 ETHERNET PHY
- 18
- PRG/CPSW RGMII2 ETHERNET PHY
- 19
- BOOSTERPACK CONNECTOR
- 20
- TEST AUTOMATION HEADER
- 21
- BOOT MODE BUFFER & SWITCHES
- 22
- XDS110 DEBUGGER
- 23
- INDUSTRIAL COMMUNICATION  LED's
- 24
- SoC Digital POWER & DECAPs
- 25
- SoC Analog POWER & DECAPs
- 26
- BOARD POWER INPUT & USB2.0
- 27
- BOARD POWER_01
- 28
- BOARD POWER_02
- 29
- HARDWARE SCHEMATICS
sheet 2
- REVISION HISTORY
- VER #
- DATE
- DESCRIPTION OF CHANGES
- AUTHOR
- REVIEWED  BY
- APPROVED  BY
- 0.1
- 15th APR 2021
- Drafted from PROC109E1 v3.1
- Mistral Design Team
- ADC Capacitors value is changed to 100pF from 1000pF as per TI's Review comment.
- 0.2
- 15th APR 2021
- Updated the FSI Header pinout as per
- Mistral Design Team
- 0.3
- 16th APR 2021
- Changed the VBias supply of LDO U33 (TPS74801DRCR) to 5V from 3.3V
- Mistral Design Team
- 1.Changed the LDO U5 (TPS7A2518DRVR) to TPS74601PDRVR as there
  was an overshoot observed in the former.
  2.R584 (47.5k) & R585 (21k) added as feedback resistors for U5.
  3.U18 value and Mfg PN changed to XAM2434ASFGGAALX.
  4.Boosterpack Connector pinouts (J2.2 & J4.10) block diagram updated as per SCH.
- 0.4
- 21st APR 2021
- Mistral Design Team
- 0.5
- 23rd APR 2021
- Pull up(R588,R590)/Pull down(R589,R591) resistors option provided for
  BOOTMODE14 and BOOTMODE15 signals.
  R586 and R587 added to isolate the BOOTMODE signals after latching
- Mistral Design Team
- Reverted the VDD_1V8 LDO circuit to E1 (TPS7A2518DRVR) design as the newly
  selected part is no stock available
- 0.6
- 27th APR 2021
- Mistral Design Team
- 0.7
- 30th APR 2021
- 1.Test Points(TP40-TP53) added for all probing points which had components as reference.
  2.R272,R273,R274,R279,R280,R281 changed from 1K to 49.9K as per TXB0106RGYR datasheet
  and TI's recommendation as the strong pull up provided on signals from
  Header J12 and J21 ends up in improper level translation.
- Mistral Design Team
- 0.8
- 4th MAY 2021
- R592-100K pull down added to MAIN_UART0_TXD signal to avoid junk values
- Mistral Design Team
- 0.9
- 24th MAY 2021
- Alternates updated
- Mistral Design Team
- 1.0
- 08th JUN 2021
- Baselined for E2
- Mistral Design Team
sheet 3
- BLOCK DIAGRAM
sheet 4
- POWER TREE
sheet 5
- POWER ON SEQUENCE
sheet 6
- RESET ARCHITECTURE
sheet 7
- GPIO MAPPING TABLE
sheet 8
- I2C TREE
sheet 9
- BOOSTERPACK CONNECTOR PINOUTs
sheet 10
- Reset Inputs
- MCU PORz Input
- Voltage monitor asserts the corresponding
  reset Signals low if :
- VDD_1V8 < 1.692V
  VSYS_3V3 < 3.12V
  VDD_CORE_0V85 < 0.794477V & VDD_CORE_0V85 > 0.90823V
- Delay for PORz is set 10.41 ms
- Reset Inputs from Boosterpacks
- PORz Input Push Button
- (From test Automation Header)
- SoC Warm Reset Input
- MCU Warm Reset Input
- User Push Button
- MCU Warm Reset Input Push Button
- SoC Warm Reset Input Push Button
- User Interrupt Input Push Button
- (From test Automation Header)
- (From test Automation Header)
- DEBOUNCE CIRCUIT
sheet 11
- SoC Blocks
- LPF For I2C Pins
- GPIO1_54
- GPIO1_55
- OBSCLK is used to source the RGMII2 Ethernet PHY
- Mount R243 & R264 and DNI R242 & R273 to source the RGMII2
  Ethernet PHY from OBSCLK
- LPF Designed for 25MHz Cutoff
  Have to change resistor and capacitor values accordingly
- UART Buffer & EXT UART HDR for UART1
- SoC_Connections
- Header_Connections
- MAIN_UART1_TXD
- UART1_HDR_RXD - Pin5
- GPIO1_25
- MAIN_UART1_RXD
- UART1_HDR_TXD - Pin4
- MAIN_UART1_RTS#
- UART1_HDR_CTS# - Pin2
- GPIO1_28
- MAIN_UART1_CTS#
- UART1_HDR_RTS# - Pin6
- Isolation Buffer for Bootmode Input pins
- BOOT Mode Pins
- GPIO1_38
- GPIO1_39
- GPIO0_22
- GPIO0_26
- GPIO0_27
- GPIO0_28
- (To FSI Header)
- Note : No Input to SoC should be driven
  from others while Booting
- Note: 1K resistors are used to isolate the
  BOOTMODE control logic after the value is latched
